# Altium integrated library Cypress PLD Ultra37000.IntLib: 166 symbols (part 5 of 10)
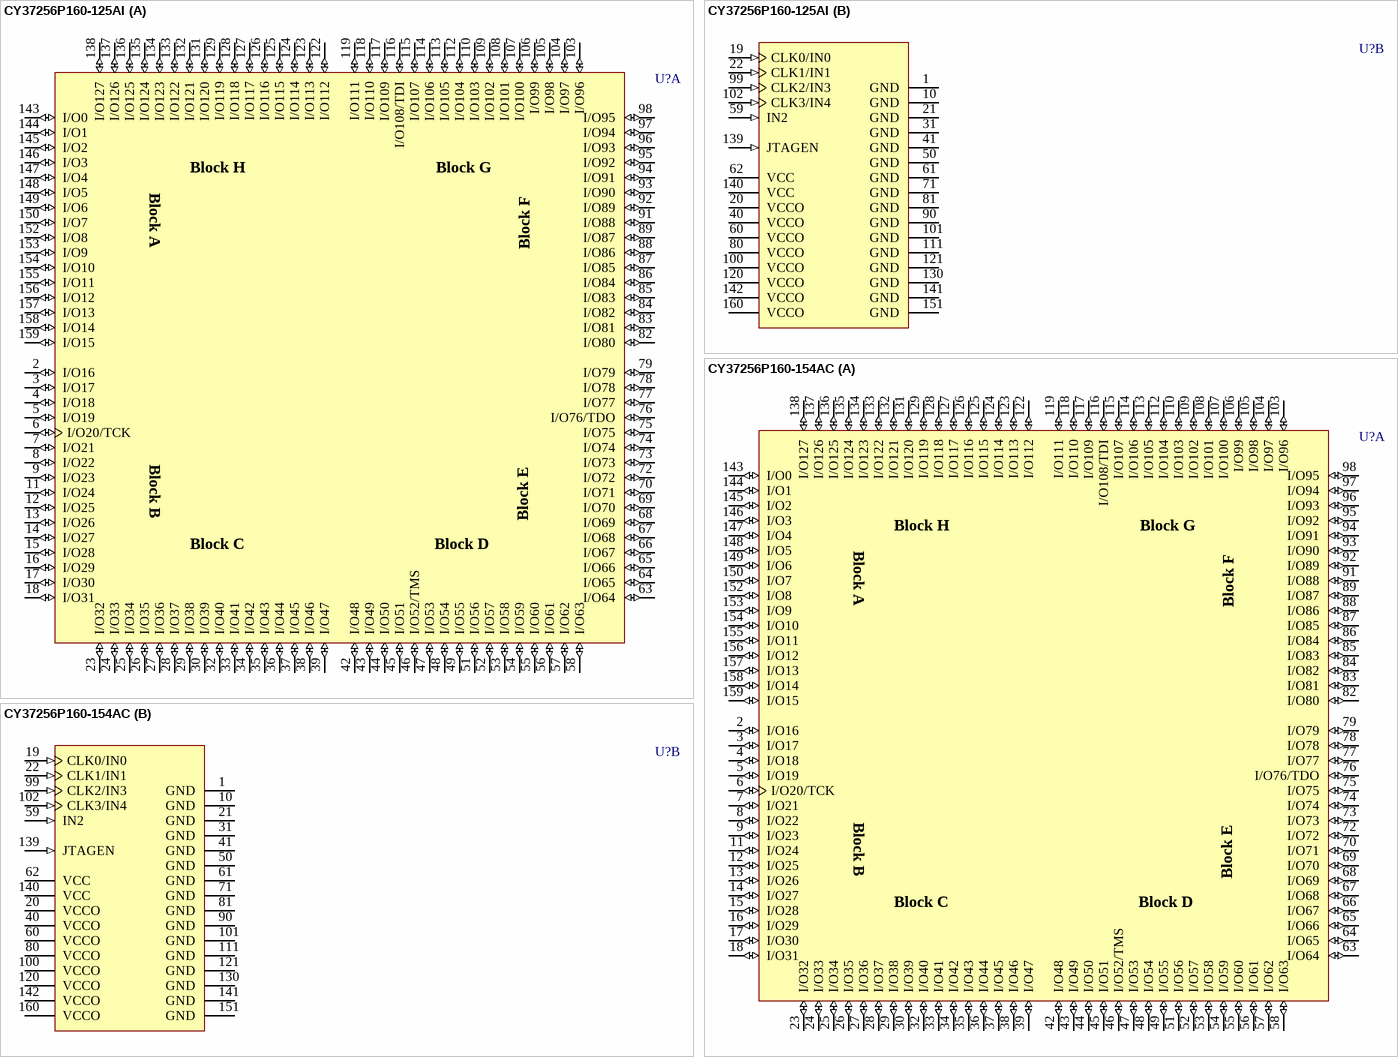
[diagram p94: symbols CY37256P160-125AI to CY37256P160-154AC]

## CY37256P160-154AC
designator U?
Ultra37000 5V, ISR High-Performance CPLD
footprint A160_N (Thin QFP, 160-Leads, Body 24x24mm, Pitch 0.5mm, IPC Medium Density)
footprint A160_L (Thin QFP, 160-Leads, Body 24x24mm, Pitch 0.5mm, IPC High Density)
footprint A160_M (Thin QFP, 160-Leads, Body 24x24mm, Pitch 0.5mm, IPC Low Density)
3D model CY37256P160-A160 (160-Pin Thin Quad Flat Pack 0.5 mm Pitch)
part A pins: 2 I/O16 (io), 3 I/O17 (io), 4 I/O18 (io), 5 I/O19 (io), 6 I/O20/TCK (io), 7 I/O21 (io), 8 I/O22 (io), 9 I/O23 (io), 11 I/O24 (io), 12 I/O25 (io), 13 I/O26 (io), 14 I/O27 (io), 15 I/O28 (io), 16 I/O29 (io), 17 I/O30 (io), 18 I/O31 (io), 23 I/O32 (io), 24 I/O33 (io), 25 I/O34 (io), 26 I/O35 (io), 27 I/O36 (io), 28 I/O37 (io), 29 I/O38 (io), 30 I/O39 (io), 32 I/O40 (io), 33 I/O41 (io), 34 I/O42 (io), 35 I/O43 (io), 36 I/O44 (io), 37 I/O45 (io), 38 I/O46 (io), 39 I/O47 (io), 42 I/O48 (io), 43 I/O49 (io), 44 I/O50 (io), 45 I/O51 (io), 46 I/O52/TMS (io), 47 I/O53 (io), 48 I/O54 (io), 49 I/O55 (io), 51 I/O56 (io), 52 I/O57 (io), 53 I/O58 (io), 54 I/O59 (io), 55 I/O60 (io), 56 I/O61 (io), 57 I/O62 (io), 58 I/O63 (io), 63 I/O64 (io), 64 I/O65 (io), 65 I/O66 (io), 66 I/O67 (io), 67 I/O68 (io), 68 I/O69 (io), 69 I/O70 (io), 70 I/O71 (io), 72 I/O72 (io), 73 I/O73 (io), 74 I/O74 (io), 75 I/O75 (io), 76 I/O76/TDO (io), 77 I/O77 (io), 78 I/O78 (io), 79 I/O79 (io), 82 I/O80 (io), 83 I/O81 (io), 84 I/O82 (io), 85 I/O83 (io), 86 I/O84 (io), 87 I/O85 (io), 88 I/O86 (io), 89 I/O87 (io), 91 I/O88 (io), 92 I/O89 (io), 93 I/O90 (io), 94 I/O91 (io), 95 I/O92 (io), 96 I/O93 (io), 97 I/O94 (io), 98 I/O95 (io), 103 I/O96 (io), 104 I/O97 (io), 105 I/O98 (io), 106 I/O99 (io), 107 I/O100 (io), 108 I/O101 (io), 109 I/O102 (io), 110 I/O103 (io), 112 I/O104 (io), 113 I/O105 (io), 114 I/O106 (io), 115 I/O107 (io), 116 I/O108/TDI (io), 117 I/O109 (io), 118 I/O110 (io), 119 I/O111 (io), 122 I/O112 (io), 123 I/O113 (io), 124 I/O114 (io), 125 I/O115 (io), 126 I/O116 (io), 127 I/O117 (io), 128 I/O118 (io), 129 I/O119 (io), 131 I/O120 (io), 132 I/O121 (io), 133 I/O122 (io), 134 I/O123 (io), 135 I/O124 (io), 136 I/O125 (io), 137 I/O126 (io), 138 I/O127 (io), 143 I/O0 (io), 144 I/O1 (io), 145 I/O2 (io), 146 I/O3 (io), 147 I/O4 (io), 148 I/O5 (io), 149 I/O6 (io), 150 I/O7 (io), 152 I/O8 (io), 153 I/O9 (io), 154 I/O10 (io), 155 I/O11 (io), 156 I/O12 (io), 157 I/O13 (io), 158 I/O14 (io), 159 I/O15 (io)
part B pins: 1 GND (power), 10 GND (power), 19 CLK0/IN0 (in), 20 VCCO (power), 21 GND (power), 22 CLK1/IN1 (in), 31 GND (power), 40 VCCO (power), 41 GND (power), 50 GND (power), 59 IN2 (in), 60 VCCO (power), 61 GND (power), 62 VCC (power), 71 GND (power), 80 VCCO (power), 81 GND (power), 90 GND (power), 99 CLK2/IN3 (in), 100 VCCO (power), 101 GND (power), 102 CLK3/IN4 (in), 111 GND (power), 120 VCCO (power), 121 GND (power), 130 GND (power), 139 JTAGEN (in), 140 VCC (power), 141 GND (power), 142 VCCO (power), 151 GND (power), 160 VCCO (power)

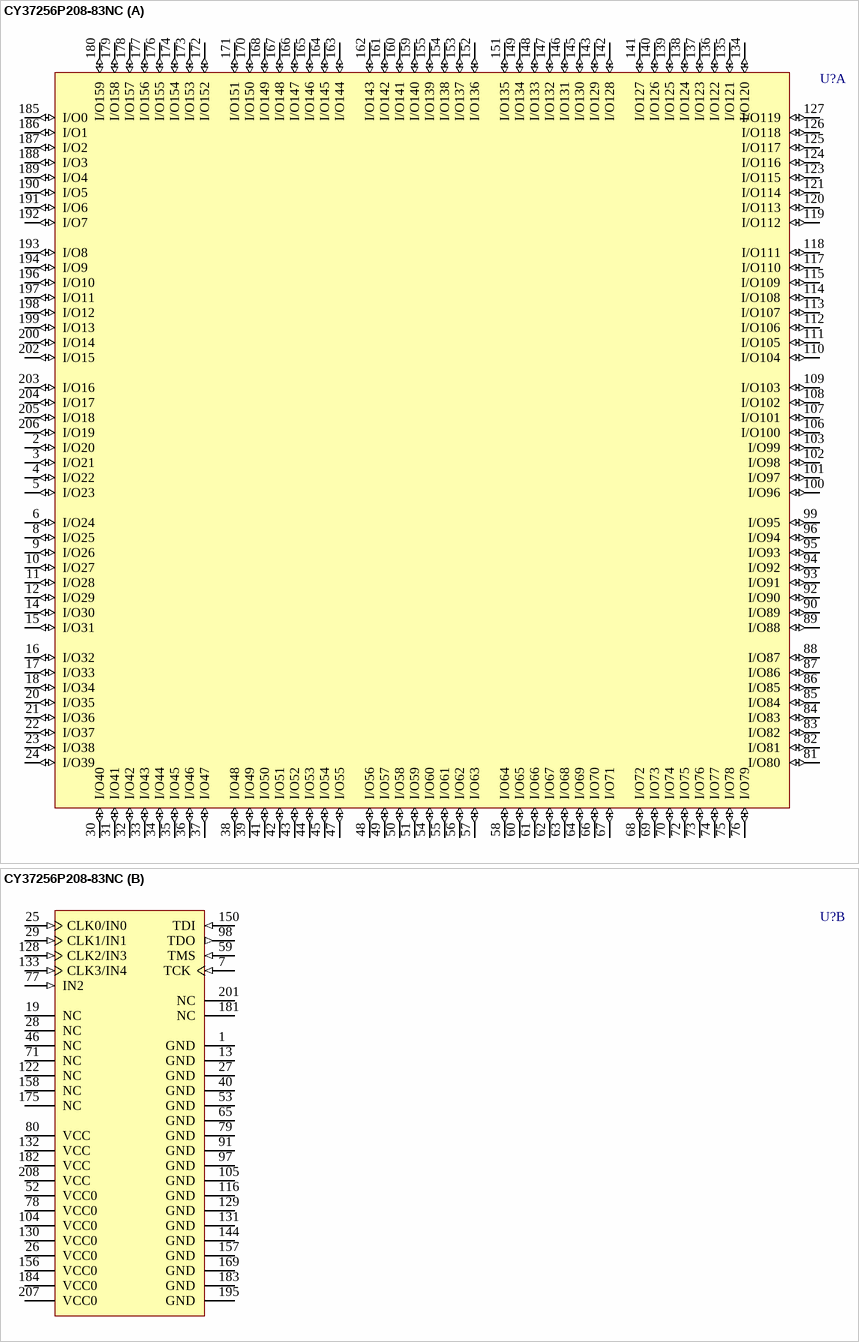
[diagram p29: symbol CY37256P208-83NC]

## CY37256P208-83NC
designator U?
Ultra37000 5V, ISR High-Performance CPLD
footprint N208_N (Shrink QFP, 208-Leads, Body 28x28mm, Pitch 0.5mm, IPC Medium Density)
footprint N208_L (Shrink QFP, 208-Leads, Body 28x28mm, Pitch 0.5mm, IPC High Density)
footprint N208_M (Shrink QFP, 208-Leads, Body 28x28mm, Pitch 0.5mm, IPC Low Density)
3D model CY37256P208-N208 (208-Pin Plastic Shrink Quad Flat Pack 0.5 mm Pitch)
part A pins: 2 I/O20 (io), 3 I/O21 (io), 4 I/O22 (io), 5 I/O23 (io), 6 I/O24 (io), 8 I/O25 (io), 9 I/O26 (io), 10 I/O27 (io), 11 I/O28 (io), 12 I/O29 (io), 14 I/O30 (io), 15 I/O31 (io), 16 I/O32 (io), 17 I/O33 (io), 18 I/O34 (io), 20 I/O35 (io), 21 I/O36 (io), 22 I/O37 (io), 23 I/O38 (io), 24 I/O39 (io), 30 I/O40 (io), 31 I/O41 (io), 32 I/O42 (io), 33 I/O43 (io), 34 I/O44 (io), 35 I/O45 (io), 36 I/O46 (io), 37 I/O47 (io), 38 I/O48 (io), 39 I/O49 (io), 41 I/O50 (io), 42 I/O51 (io), 43 I/O52 (io), 44 I/O53 (io), 45 I/O54 (io), 47 I/O55 (io), 48 I/O56 (io), 49 I/O57 (io), 50 I/O58 (io), 51 I/O59 (io), 54 I/O60 (io), 55 I/O61 (io), 56 I/O62 (io), 57 I/O63 (io), 58 I/O64 (io), 60 I/O65 (io), 61 I/O66 (io), 62 I/O67 (io), 63 I/O68 (io), 64 I/O69 (io), 66 I/O70 (io), 67 I/O71 (io), 68 I/O72 (io), 69 I/O73 (io), 70 I/O74 (io), 72 I/O75 (io), 73 I/O76 (io), 74 I/O77 (io), 75 I/O78 (io), 76 I/O79 (io), 81 I/O80 (io), 82 I/O81 (io), 83 I/O82 (io), 84 I/O83 (io), 85 I/O84 (io), 86 I/O85 (io), 87 I/O86 (io), 88 I/O87 (io), 89 I/O88 (io), 90 I/O89 (io), 92 I/O90 (io), 93 I/O91 (io), 94 I/O92 (io), 95 I/O93 (io), 96 I/O94 (io), 99 I/O95 (io), 100 I/O96 (io), 101 I/O97 (io), 102 I/O98 (io), 103 I/O99 (io), 106 I/O100 (io), 107 I/O101 (io), 108 I/O102 (io), 109 I/O103 (io), 110 I/O104 (io), 111 I/O105 (io), 112 I/O106 (io), 113 I/O107 (io), 114 I/O108 (io), 115 I/O109 (io), 117 I/O110 (io), 118 I/O111 (io), 119 I/O112 (io), 120 I/O113 (io), 121 I/O114 (io), 123 I/O115 (io), 124 I/O116 (io), 125 I/O117 (io), 126 I/O118 (io), 127 I/O119 (io), 134 I/O120 (io), 135 I/O121 (io), 136 I/O122 (io), 137 I/O123 (io), 138 I/O124 (io), 139 I/O125 (io), 140 I/O126 (io), 141 I/O127 (io), 142 I/O128 (io), 143 I/O129 (io), 145 I/O130 (io), 146 I/O131 (io), 147 I/O132 (io), 148 I/O133 (io), 149 I/O134 (io), 151 I/O135 (io), 152 I/O136 (io), 153 I/O137 (io), 154 I/O138 (io), 155 I/O139 (io), 159 I/O140 (io), 160 I/O141 (io), 161 I/O142 (io), 162 I/O143 (io), 163 I/O144 (io), 164 I/O145 (io), 165 I/O146 (io), 166 I/O147 (io), 167 I/O148 (io), 168 I/O149 (io), 170 I/O150 (io), 171 I/O151 (io), 172 I/O152 (io), 173 I/O153 (io), 174 I/O154 (io), 176 I/O155 (io), 177 I/O156 (io), 178 I/O157 (io), 179 I/O158 (io), 180 I/O159 (io), 185 I/O0 (io), 186 I/O1 (io), 187 I/O2 (io), 188 I/O3 (io), 189 I/O4 (io), 190 I/O5 (io), 191 I/O6 (io), 192 I/O7 (io), 193 I/O8 (io), 194 I/O9 (io), 196 I/O10 (io), 197 I/O11 (io), 198 I/O12 (io), 199 I/O13 (io), 200 I/O14 (io), 202 I/O15 (io), 203 I/O16 (io), 204 I/O17 (io), 205 I/O18 (io), 206 I/O19 (io)
part B pins: 1 GND (power), 7 TCK (in), 13 GND (power), 19 NC, 25 CLK0/IN0 (in), 26 VCC0 (power), 27 GND (power), 28 NC, 29 CLK1/IN1 (in), 40 GND (power), 46 NC, 52 VCC0 (power), 53 GND (power), 59 TMS (in), 65 GND (power), 71 NC, 77 IN2 (in), 78 VCC0 (power), 79 GND (power), 80 VCC (power), 91 GND (power), 97 GND (power), 98 TDO (out), 104 VCC0 (power), 105 GND (power), 116 GND (power), 122 NC, 128 CLK2/IN3 (in), 129 GND (power), 130 VCC0 (power), 131 GND (power), 132 VCC (power), 133 CLK3/IN4 (in), 144 GND (power), 150 TDI (in), 156 VCC0 (power), 157 GND (power), 158 NC, 169 GND (power), 175 NC, 181 NC, 182 VCC (power), 183 GND (power), 184 VCC0 (power), 195 GND (power), 201 NC, 207 VCC0 (power), 208 VCC (power)

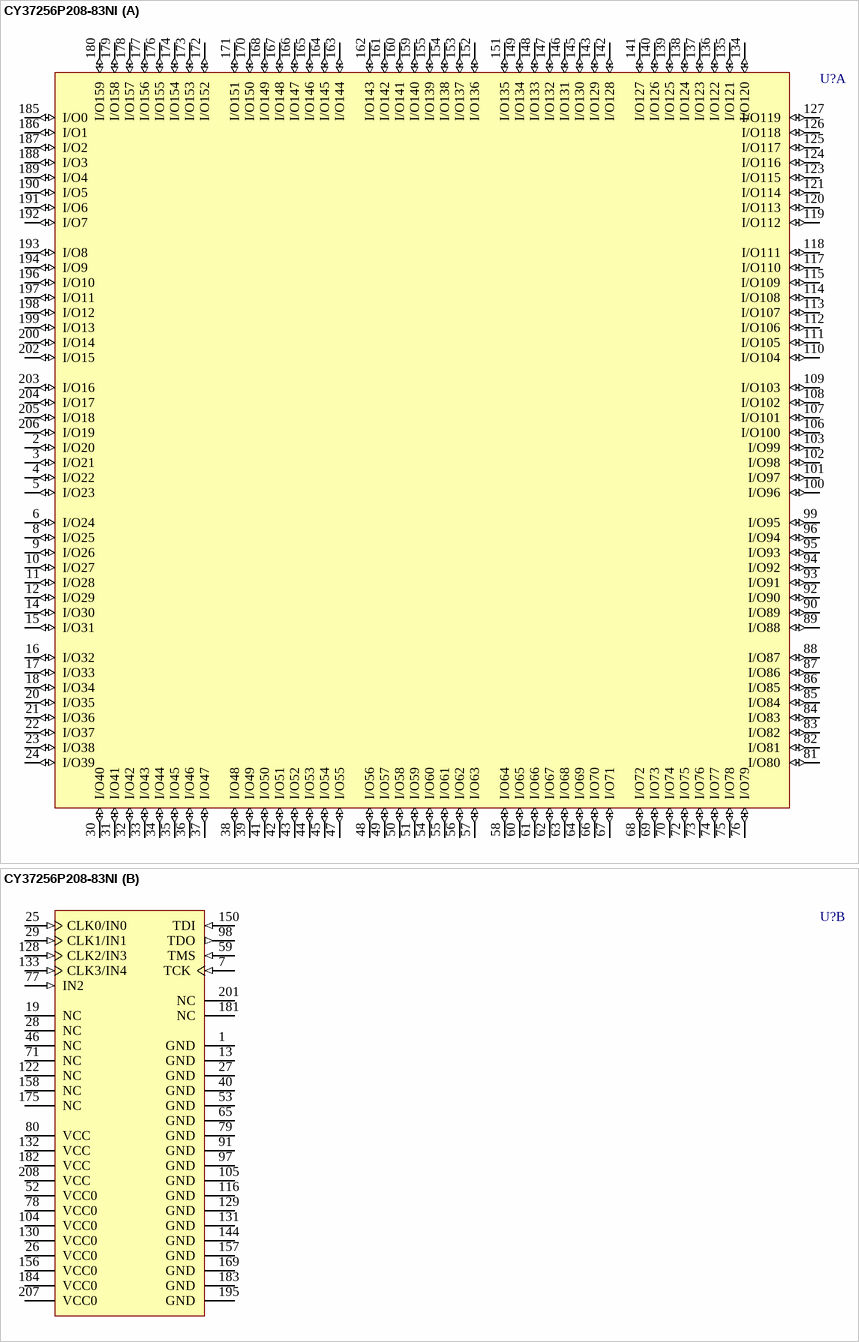
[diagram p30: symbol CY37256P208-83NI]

## CY37256P208-83NI
designator U?
Ultra37000 5V, ISR High-Performance CPLD
footprint N208_N (Shrink QFP, 208-Leads, Body 28x28mm, Pitch 0.5mm, IPC Medium Density)
footprint N208_L (Shrink QFP, 208-Leads, Body 28x28mm, Pitch 0.5mm, IPC High Density)
footprint N208_M (Shrink QFP, 208-Leads, Body 28x28mm, Pitch 0.5mm, IPC Low Density)
3D model CY37256P208-N208 (208-Pin Plastic Shrink Quad Flat Pack 0.5 mm Pitch)
part A pins: 2 I/O20 (io), 3 I/O21 (io), 4 I/O22 (io), 5 I/O23 (io), 6 I/O24 (io), 8 I/O25 (io), 9 I/O26 (io), 10 I/O27 (io), 11 I/O28 (io), 12 I/O29 (io), 14 I/O30 (io), 15 I/O31 (io), 16 I/O32 (io), 17 I/O33 (io), 18 I/O34 (io), 20 I/O35 (io), 21 I/O36 (io), 22 I/O37 (io), 23 I/O38 (io), 24 I/O39 (io), 30 I/O40 (io), 31 I/O41 (io), 32 I/O42 (io), 33 I/O43 (io), 34 I/O44 (io), 35 I/O45 (io), 36 I/O46 (io), 37 I/O47 (io), 38 I/O48 (io), 39 I/O49 (io), 41 I/O50 (io), 42 I/O51 (io), 43 I/O52 (io), 44 I/O53 (io), 45 I/O54 (io), 47 I/O55 (io), 48 I/O56 (io), 49 I/O57 (io), 50 I/O58 (io), 51 I/O59 (io), 54 I/O60 (io), 55 I/O61 (io), 56 I/O62 (io), 57 I/O63 (io), 58 I/O64 (io), 60 I/O65 (io), 61 I/O66 (io), 62 I/O67 (io), 63 I/O68 (io), 64 I/O69 (io), 66 I/O70 (io), 67 I/O71 (io), 68 I/O72 (io), 69 I/O73 (io), 70 I/O74 (io), 72 I/O75 (io), 73 I/O76 (io), 74 I/O77 (io), 75 I/O78 (io), 76 I/O79 (io), 81 I/O80 (io), 82 I/O81 (io), 83 I/O82 (io), 84 I/O83 (io), 85 I/O84 (io), 86 I/O85 (io), 87 I/O86 (io), 88 I/O87 (io), 89 I/O88 (io), 90 I/O89 (io), 92 I/O90 (io), 93 I/O91 (io), 94 I/O92 (io), 95 I/O93 (io), 96 I/O94 (io), 99 I/O95 (io), 100 I/O96 (io), 101 I/O97 (io), 102 I/O98 (io), 103 I/O99 (io), 106 I/O100 (io), 107 I/O101 (io), 108 I/O102 (io), 109 I/O103 (io), 110 I/O104 (io), 111 I/O105 (io), 112 I/O106 (io), 113 I/O107 (io), 114 I/O108 (io), 115 I/O109 (io), 117 I/O110 (io), 118 I/O111 (io), 119 I/O112 (io), 120 I/O113 (io), 121 I/O114 (io), 123 I/O115 (io), 124 I/O116 (io), 125 I/O117 (io), 126 I/O118 (io), 127 I/O119 (io), 134 I/O120 (io), 135 I/O121 (io), 136 I/O122 (io), 137 I/O123 (io), 138 I/O124 (io), 139 I/O125 (io), 140 I/O126 (io), 141 I/O127 (io), 142 I/O128 (io), 143 I/O129 (io), 145 I/O130 (io), 146 I/O131 (io), 147 I/O132 (io), 148 I/O133 (io), 149 I/O134 (io), 151 I/O135 (io), 152 I/O136 (io), 153 I/O137 (io), 154 I/O138 (io), 155 I/O139 (io), 159 I/O140 (io), 160 I/O141 (io), 161 I/O142 (io), 162 I/O143 (io), 163 I/O144 (io), 164 I/O145 (io), 165 I/O146 (io), 166 I/O147 (io), 167 I/O148 (io), 168 I/O149 (io), 170 I/O150 (io), 171 I/O151 (io), 172 I/O152 (io), 173 I/O153 (io), 174 I/O154 (io), 176 I/O155 (io), 177 I/O156 (io), 178 I/O157 (io), 179 I/O158 (io), 180 I/O159 (io), 185 I/O0 (io), 186 I/O1 (io), 187 I/O2 (io), 188 I/O3 (io), 189 I/O4 (io), 190 I/O5 (io), 191 I/O6 (io), 192 I/O7 (io), 193 I/O8 (io), 194 I/O9 (io), 196 I/O10 (io), 197 I/O11 (io), 198 I/O12 (io), 199 I/O13 (io), 200 I/O14 (io), 202 I/O15 (io), 203 I/O16 (io), 204 I/O17 (io), 205 I/O18 (io), 206 I/O19 (io)
part B pins: 1 GND (power), 7 TCK (in), 13 GND (power), 19 NC, 25 CLK0/IN0 (in), 26 VCC0 (power), 27 GND (power), 28 NC, 29 CLK1/IN1 (in), 40 GND (power), 46 NC, 52 VCC0 (power), 53 GND (power), 59 TMS (in), 65 GND (power), 71 NC, 77 IN2 (in), 78 VCC0 (power), 79 GND (power), 80 VCC (power), 91 GND (power), 97 GND (power), 98 TDO (out), 104 VCC0 (power), 105 GND (power), 116 GND (power), 122 NC, 128 CLK2/IN3 (in), 129 GND (power), 130 VCC0 (power), 131 GND (power), 132 VCC (power), 133 CLK3/IN4 (in), 144 GND (power), 150 TDI (in), 156 VCC0 (power), 157 GND (power), 158 NC, 169 GND (power), 175 NC, 181 NC, 182 VCC (power), 183 GND (power), 184 VCC0 (power), 195 GND (power), 201 NC, 207 VCC0 (power), 208 VCC (power)

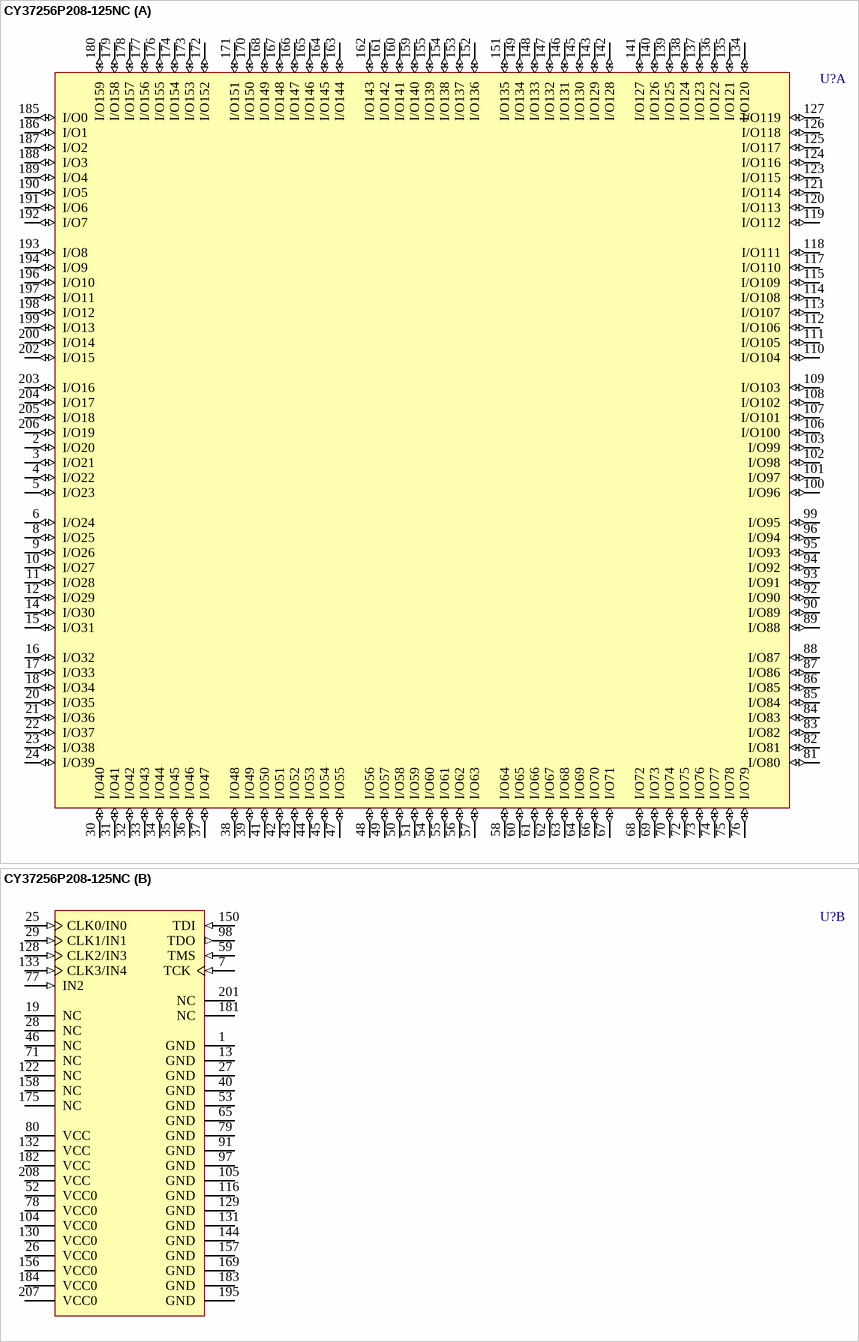
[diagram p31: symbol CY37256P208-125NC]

## CY37256P208-125NC
designator U?
Ultra37000 5V, ISR High-Performance CPLD
footprint N208_N (Shrink QFP, 208-Leads, Body 28x28mm, Pitch 0.5mm, IPC Medium Density)
footprint N208_L (Shrink QFP, 208-Leads, Body 28x28mm, Pitch 0.5mm, IPC High Density)
footprint N208_M (Shrink QFP, 208-Leads, Body 28x28mm, Pitch 0.5mm, IPC Low Density)
3D model CY37256P208-N208 (208-Pin Plastic Shrink Quad Flat Pack 0.5 mm Pitch)
part A pins: 2 I/O20 (io), 3 I/O21 (io), 4 I/O22 (io), 5 I/O23 (io), 6 I/O24 (io), 8 I/O25 (io), 9 I/O26 (io), 10 I/O27 (io), 11 I/O28 (io), 12 I/O29 (io), 14 I/O30 (io), 15 I/O31 (io), 16 I/O32 (io), 17 I/O33 (io), 18 I/O34 (io), 20 I/O35 (io), 21 I/O36 (io), 22 I/O37 (io), 23 I/O38 (io), 24 I/O39 (io), 30 I/O40 (io), 31 I/O41 (io), 32 I/O42 (io), 33 I/O43 (io), 34 I/O44 (io), 35 I/O45 (io), 36 I/O46 (io), 37 I/O47 (io), 38 I/O48 (io), 39 I/O49 (io), 41 I/O50 (io), 42 I/O51 (io), 43 I/O52 (io), 44 I/O53 (io), 45 I/O54 (io), 47 I/O55 (io), 48 I/O56 (io), 49 I/O57 (io), 50 I/O58 (io), 51 I/O59 (io), 54 I/O60 (io), 55 I/O61 (io), 56 I/O62 (io), 57 I/O63 (io), 58 I/O64 (io), 60 I/O65 (io), 61 I/O66 (io), 62 I/O67 (io), 63 I/O68 (io), 64 I/O69 (io), 66 I/O70 (io), 67 I/O71 (io), 68 I/O72 (io), 69 I/O73 (io), 70 I/O74 (io), 72 I/O75 (io), 73 I/O76 (io), 74 I/O77 (io), 75 I/O78 (io), 76 I/O79 (io), 81 I/O80 (io), 82 I/O81 (io), 83 I/O82 (io), 84 I/O83 (io), 85 I/O84 (io), 86 I/O85 (io), 87 I/O86 (io), 88 I/O87 (io), 89 I/O88 (io), 90 I/O89 (io), 92 I/O90 (io), 93 I/O91 (io), 94 I/O92 (io), 95 I/O93 (io), 96 I/O94 (io), 99 I/O95 (io), 100 I/O96 (io), 101 I/O97 (io), 102 I/O98 (io), 103 I/O99 (io), 106 I/O100 (io), 107 I/O101 (io), 108 I/O102 (io), 109 I/O103 (io), 110 I/O104 (io), 111 I/O105 (io), 112 I/O106 (io), 113 I/O107 (io), 114 I/O108 (io), 115 I/O109 (io), 117 I/O110 (io), 118 I/O111 (io), 119 I/O112 (io), 120 I/O113 (io), 121 I/O114 (io), 123 I/O115 (io), 124 I/O116 (io), 125 I/O117 (io), 126 I/O118 (io), 127 I/O119 (io), 134 I/O120 (io), 135 I/O121 (io), 136 I/O122 (io), 137 I/O123 (io), 138 I/O124 (io), 139 I/O125 (io), 140 I/O126 (io), 141 I/O127 (io), 142 I/O128 (io), 143 I/O129 (io), 145 I/O130 (io), 146 I/O131 (io), 147 I/O132 (io), 148 I/O133 (io), 149 I/O134 (io), 151 I/O135 (io), 152 I/O136 (io), 153 I/O137 (io), 154 I/O138 (io), 155 I/O139 (io), 159 I/O140 (io), 160 I/O141 (io), 161 I/O142 (io), 162 I/O143 (io), 163 I/O144 (io), 164 I/O145 (io), 165 I/O146 (io), 166 I/O147 (io), 167 I/O148 (io), 168 I/O149 (io), 170 I/O150 (io), 171 I/O151 (io), 172 I/O152 (io), 173 I/O153 (io), 174 I/O154 (io), 176 I/O155 (io), 177 I/O156 (io), 178 I/O157 (io), 179 I/O158 (io), 180 I/O159 (io), 185 I/O0 (io), 186 I/O1 (io), 187 I/O2 (io), 188 I/O3 (io), 189 I/O4 (io), 190 I/O5 (io), 191 I/O6 (io), 192 I/O7 (io), 193 I/O8 (io), 194 I/O9 (io), 196 I/O10 (io), 197 I/O11 (io), 198 I/O12 (io), 199 I/O13 (io), 200 I/O14 (io), 202 I/O15 (io), 203 I/O16 (io), 204 I/O17 (io), 205 I/O18 (io), 206 I/O19 (io)
part B pins: 1 GND (power), 7 TCK (in), 13 GND (power), 19 NC, 25 CLK0/IN0 (in), 26 VCC0 (power), 27 GND (power), 28 NC, 29 CLK1/IN1 (in), 40 GND (power), 46 NC, 52 VCC0 (power), 53 GND (power), 59 TMS (in), 65 GND (power), 71 NC, 77 IN2 (in), 78 VCC0 (power), 79 GND (power), 80 VCC (power), 91 GND (power), 97 GND (power), 98 TDO (out), 104 VCC0 (power), 105 GND (power), 116 GND (power), 122 NC, 128 CLK2/IN3 (in), 129 GND (power), 130 VCC0 (power), 131 GND (power), 132 VCC (power), 133 CLK3/IN4 (in), 144 GND (power), 150 TDI (in), 156 VCC0 (power), 157 GND (power), 158 NC, 169 GND (power), 175 NC, 181 NC, 182 VCC (power), 183 GND (power), 184 VCC0 (power), 195 GND (power), 201 NC, 207 VCC0 (power), 208 VCC (power)

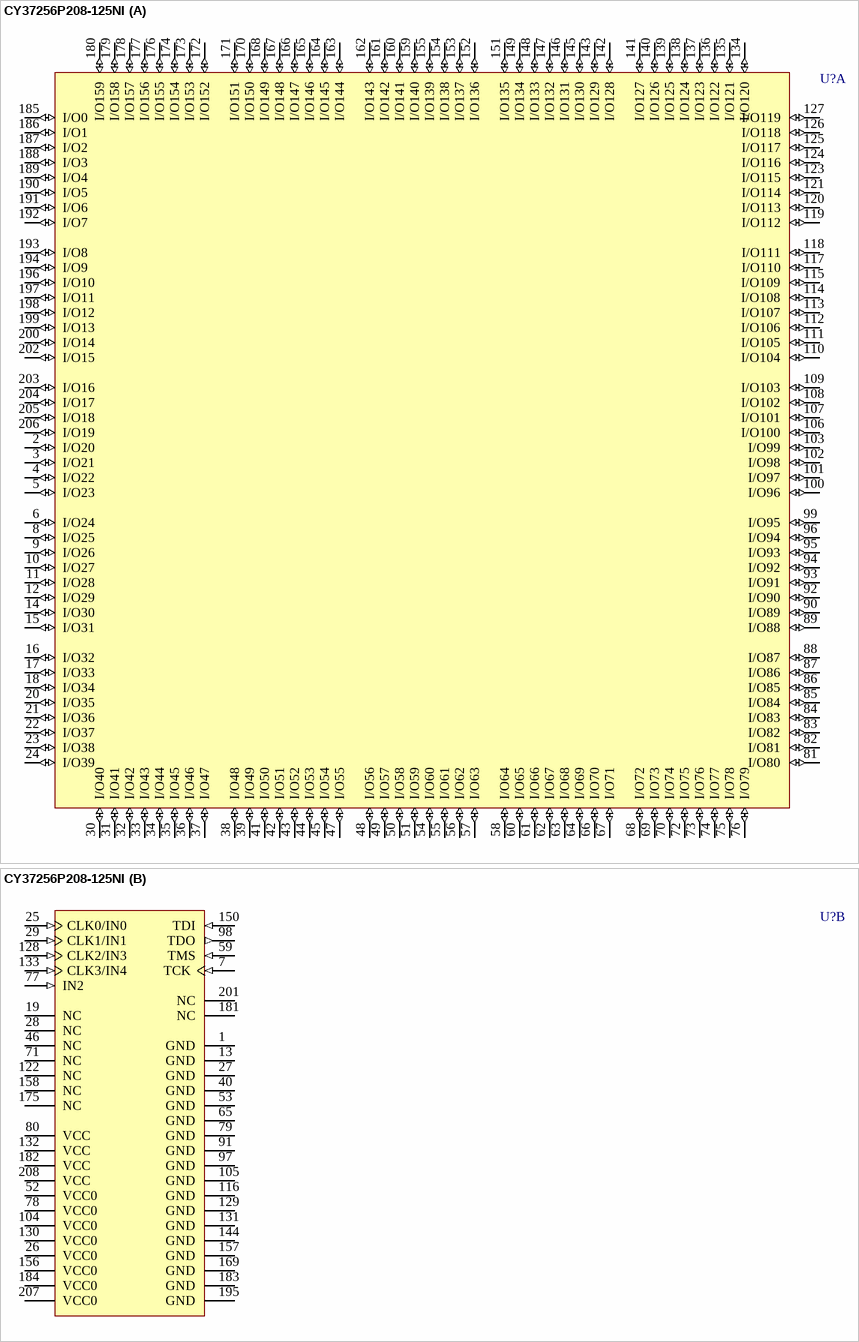
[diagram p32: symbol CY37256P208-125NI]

## CY37256P208-125NI
designator U?
Ultra37000 5V, ISR High-Performance CPLD
footprint N208_N (Shrink QFP, 208-Leads, Body 28x28mm, Pitch 0.5mm, IPC Medium Density)
footprint N208_L (Shrink QFP, 208-Leads, Body 28x28mm, Pitch 0.5mm, IPC High Density)
footprint N208_M (Shrink QFP, 208-Leads, Body 28x28mm, Pitch 0.5mm, IPC Low Density)
3D model CY37256P208-N208 (208-Pin Plastic Shrink Quad Flat Pack 0.5 mm Pitch)
part A pins: 2 I/O20 (io), 3 I/O21 (io), 4 I/O22 (io), 5 I/O23 (io), 6 I/O24 (io), 8 I/O25 (io), 9 I/O26 (io), 10 I/O27 (io), 11 I/O28 (io), 12 I/O29 (io), 14 I/O30 (io), 15 I/O31 (io), 16 I/O32 (io), 17 I/O33 (io), 18 I/O34 (io), 20 I/O35 (io), 21 I/O36 (io), 22 I/O37 (io), 23 I/O38 (io), 24 I/O39 (io), 30 I/O40 (io), 31 I/O41 (io), 32 I/O42 (io), 33 I/O43 (io), 34 I/O44 (io), 35 I/O45 (io), 36 I/O46 (io), 37 I/O47 (io), 38 I/O48 (io), 39 I/O49 (io), 41 I/O50 (io), 42 I/O51 (io), 43 I/O52 (io), 44 I/O53 (io), 45 I/O54 (io), 47 I/O55 (io), 48 I/O56 (io), 49 I/O57 (io), 50 I/O58 (io), 51 I/O59 (io), 54 I/O60 (io), 55 I/O61 (io), 56 I/O62 (io), 57 I/O63 (io), 58 I/O64 (io), 60 I/O65 (io), 61 I/O66 (io), 62 I/O67 (io), 63 I/O68 (io), 64 I/O69 (io), 66 I/O70 (io), 67 I/O71 (io), 68 I/O72 (io), 69 I/O73 (io), 70 I/O74 (io), 72 I/O75 (io), 73 I/O76 (io), 74 I/O77 (io), 75 I/O78 (io), 76 I/O79 (io), 81 I/O80 (io), 82 I/O81 (io), 83 I/O82 (io), 84 I/O83 (io), 85 I/O84 (io), 86 I/O85 (io), 87 I/O86 (io), 88 I/O87 (io), 89 I/O88 (io), 90 I/O89 (io), 92 I/O90 (io), 93 I/O91 (io), 94 I/O92 (io), 95 I/O93 (io), 96 I/O94 (io), 99 I/O95 (io), 100 I/O96 (io), 101 I/O97 (io), 102 I/O98 (io), 103 I/O99 (io), 106 I/O100 (io), 107 I/O101 (io), 108 I/O102 (io), 109 I/O103 (io), 110 I/O104 (io), 111 I/O105 (io), 112 I/O106 (io), 113 I/O107 (io), 114 I/O108 (io), 115 I/O109 (io), 117 I/O110 (io), 118 I/O111 (io), 119 I/O112 (io), 120 I/O113 (io), 121 I/O114 (io), 123 I/O115 (io), 124 I/O116 (io), 125 I/O117 (io), 126 I/O118 (io), 127 I/O119 (io), 134 I/O120 (io), 135 I/O121 (io), 136 I/O122 (io), 137 I/O123 (io), 138 I/O124 (io), 139 I/O125 (io), 140 I/O126 (io), 141 I/O127 (io), 142 I/O128 (io), 143 I/O129 (io), 145 I/O130 (io), 146 I/O131 (io), 147 I/O132 (io), 148 I/O133 (io), 149 I/O134 (io), 151 I/O135 (io), 152 I/O136 (io), 153 I/O137 (io), 154 I/O138 (io), 155 I/O139 (io), 159 I/O140 (io), 160 I/O141 (io), 161 I/O142 (io), 162 I/O143 (io), 163 I/O144 (io), 164 I/O145 (io), 165 I/O146 (io), 166 I/O147 (io), 167 I/O148 (io), 168 I/O149 (io), 170 I/O150 (io), 171 I/O151 (io), 172 I/O152 (io), 173 I/O153 (io), 174 I/O154 (io), 176 I/O155 (io), 177 I/O156 (io), 178 I/O157 (io), 179 I/O158 (io), 180 I/O159 (io), 185 I/O0 (io), 186 I/O1 (io), 187 I/O2 (io), 188 I/O3 (io), 189 I/O4 (io), 190 I/O5 (io), 191 I/O6 (io), 192 I/O7 (io), 193 I/O8 (io), 194 I/O9 (io), 196 I/O10 (io), 197 I/O11 (io), 198 I/O12 (io), 199 I/O13 (io), 200 I/O14 (io), 202 I/O15 (io), 203 I/O16 (io), 204 I/O17 (io), 205 I/O18 (io), 206 I/O19 (io)
part B pins: 1 GND (power), 7 TCK (in), 13 GND (power), 19 NC, 25 CLK0/IN0 (in), 26 VCC0 (power), 27 GND (power), 28 NC, 29 CLK1/IN1 (in), 40 GND (power), 46 NC, 52 VCC0 (power), 53 GND (power), 59 TMS (in), 65 GND (power), 71 NC, 77 IN2 (in), 78 VCC0 (power), 79 GND (power), 80 VCC (power), 91 GND (power), 97 GND (power), 98 TDO (out), 104 VCC0 (power), 105 GND (power), 116 GND (power), 122 NC, 128 CLK2/IN3 (in), 129 GND (power), 130 VCC0 (power), 131 GND (power), 132 VCC (power), 133 CLK3/IN4 (in), 144 GND (power), 150 TDI (in), 156 VCC0 (power), 157 GND (power), 158 NC, 169 GND (power), 175 NC, 181 NC, 182 VCC (power), 183 GND (power), 184 VCC0 (power), 195 GND (power), 201 NC, 207 VCC0 (power), 208 VCC (power)

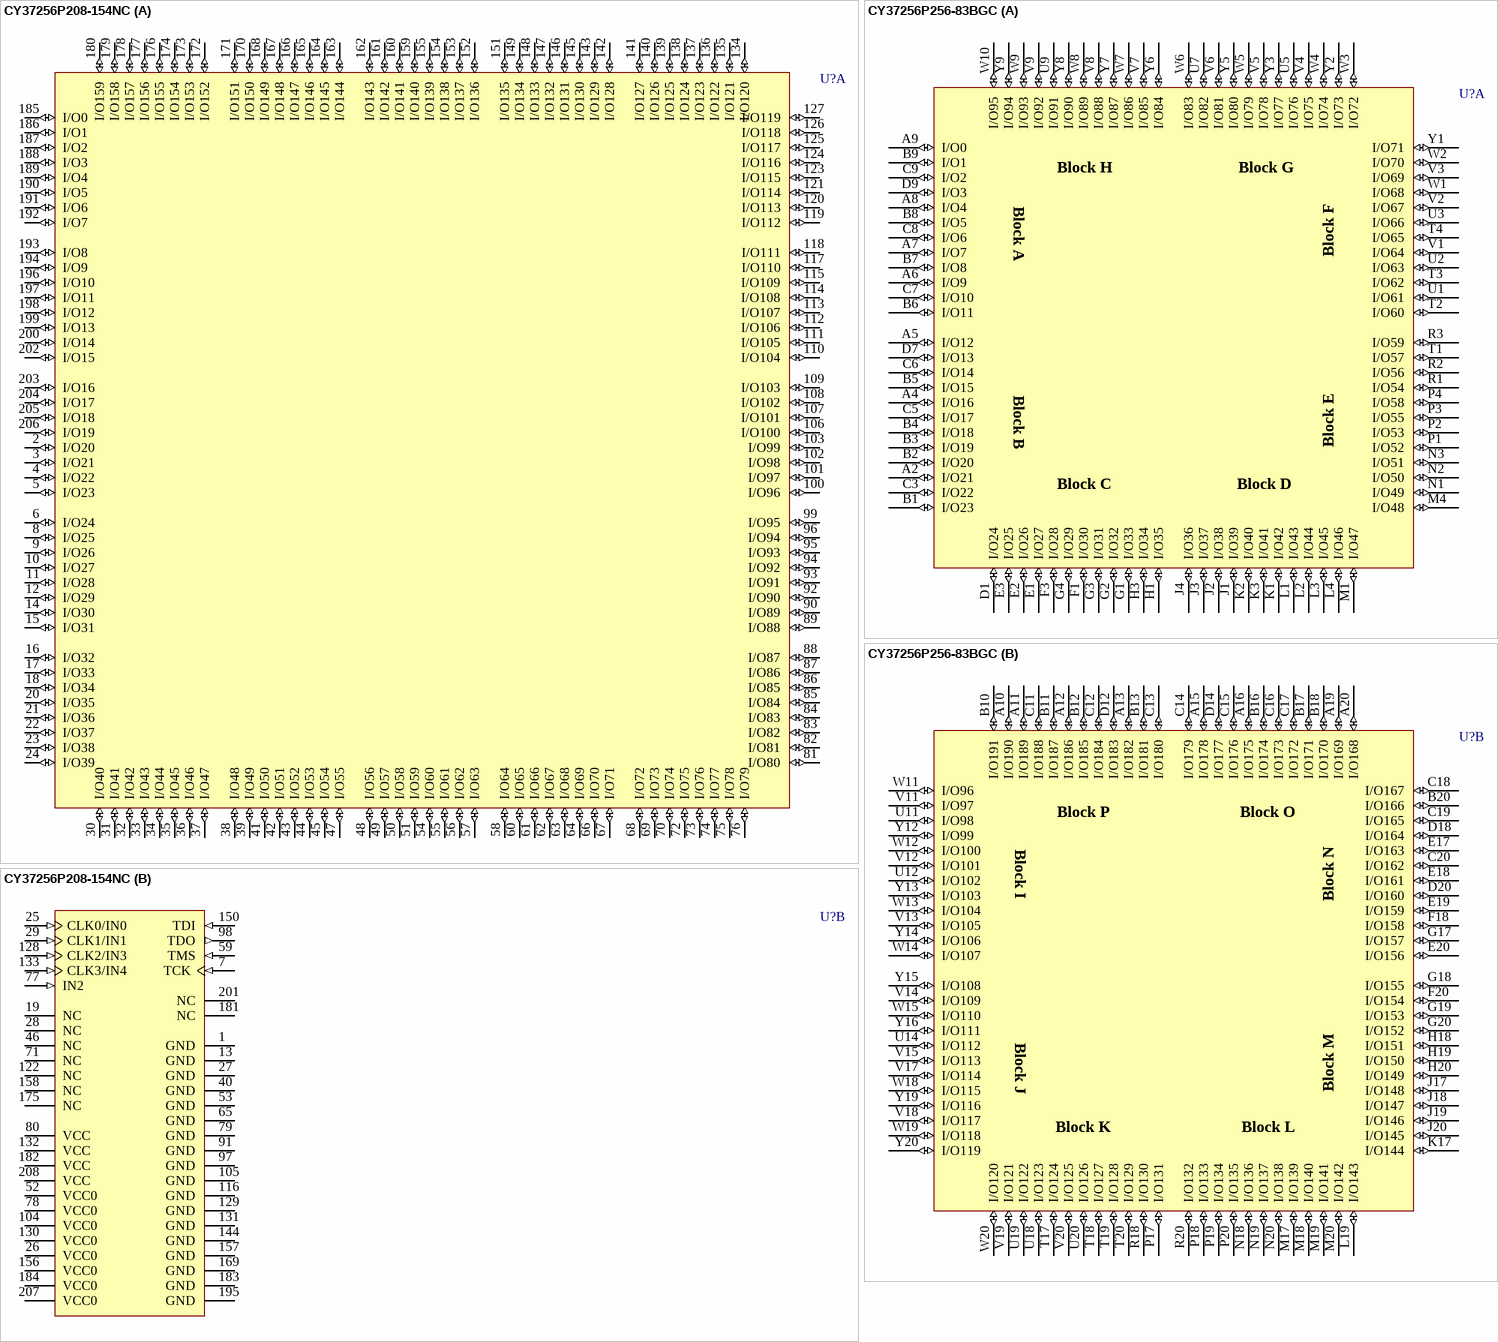
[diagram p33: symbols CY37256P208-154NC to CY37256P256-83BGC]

## CY37256P208-154NC
designator U?
Ultra37000 5V, ISR High-Performance CPLD
footprint N208_N (Shrink QFP, 208-Leads, Body 28x28mm, Pitch 0.5mm, IPC Medium Density)
footprint N208_L (Shrink QFP, 208-Leads, Body 28x28mm, Pitch 0.5mm, IPC High Density)
footprint N208_M (Shrink QFP, 208-Leads, Body 28x28mm, Pitch 0.5mm, IPC Low Density)
3D model CY37256P208-N208 (208-Pin Plastic Shrink Quad Flat Pack 0.5 mm Pitch)
part A pins: 2 I/O20 (io), 3 I/O21 (io), 4 I/O22 (io), 5 I/O23 (io), 6 I/O24 (io), 8 I/O25 (io), 9 I/O26 (io), 10 I/O27 (io), 11 I/O28 (io), 12 I/O29 (io), 14 I/O30 (io), 15 I/O31 (io), 16 I/O32 (io), 17 I/O33 (io), 18 I/O34 (io), 20 I/O35 (io), 21 I/O36 (io), 22 I/O37 (io), 23 I/O38 (io), 24 I/O39 (io), 30 I/O40 (io), 31 I/O41 (io), 32 I/O42 (io), 33 I/O43 (io), 34 I/O44 (io), 35 I/O45 (io), 36 I/O46 (io), 37 I/O47 (io), 38 I/O48 (io), 39 I/O49 (io), 41 I/O50 (io), 42 I/O51 (io), 43 I/O52 (io), 44 I/O53 (io), 45 I/O54 (io), 47 I/O55 (io), 48 I/O56 (io), 49 I/O57 (io), 50 I/O58 (io), 51 I/O59 (io), 54 I/O60 (io), 55 I/O61 (io), 56 I/O62 (io), 57 I/O63 (io), 58 I/O64 (io), 60 I/O65 (io), 61 I/O66 (io), 62 I/O67 (io), 63 I/O68 (io), 64 I/O69 (io), 66 I/O70 (io), 67 I/O71 (io), 68 I/O72 (io), 69 I/O73 (io), 70 I/O74 (io), 72 I/O75 (io), 73 I/O76 (io), 74 I/O77 (io), 75 I/O78 (io), 76 I/O79 (io), 81 I/O80 (io), 82 I/O81 (io), 83 I/O82 (io), 84 I/O83 (io), 85 I/O84 (io), 86 I/O85 (io), 87 I/O86 (io), 88 I/O87 (io), 89 I/O88 (io), 90 I/O89 (io), 92 I/O90 (io), 93 I/O91 (io), 94 I/O92 (io), 95 I/O93 (io), 96 I/O94 (io), 99 I/O95 (io), 100 I/O96 (io), 101 I/O97 (io), 102 I/O98 (io), 103 I/O99 (io), 106 I/O100 (io), 107 I/O101 (io), 108 I/O102 (io), 109 I/O103 (io), 110 I/O104 (io), 111 I/O105 (io), 112 I/O106 (io), 113 I/O107 (io), 114 I/O108 (io), 115 I/O109 (io), 117 I/O110 (io), 118 I/O111 (io), 119 I/O112 (io), 120 I/O113 (io), 121 I/O114 (io), 123 I/O115 (io), 124 I/O116 (io), 125 I/O117 (io), 126 I/O118 (io), 127 I/O119 (io), 134 I/O120 (io), 135 I/O121 (io), 136 I/O122 (io), 137 I/O123 (io), 138 I/O124 (io), 139 I/O125 (io), 140 I/O126 (io), 141 I/O127 (io), 142 I/O128 (io), 143 I/O129 (io), 145 I/O130 (io), 146 I/O131 (io), 147 I/O132 (io), 148 I/O133 (io), 149 I/O134 (io), 151 I/O135 (io), 152 I/O136 (io), 153 I/O137 (io), 154 I/O138 (io), 155 I/O139 (io), 159 I/O140 (io), 160 I/O141 (io), 161 I/O142 (io), 162 I/O143 (io), 163 I/O144 (io), 164 I/O145 (io), 165 I/O146 (io), 166 I/O147 (io), 167 I/O148 (io), 168 I/O149 (io), 170 I/O150 (io), 171 I/O151 (io), 172 I/O152 (io), 173 I/O153 (io), 174 I/O154 (io), 176 I/O155 (io), 177 I/O156 (io), 178 I/O157 (io), 179 I/O158 (io), 180 I/O159 (io), 185 I/O0 (io), 186 I/O1 (io), 187 I/O2 (io), 188 I/O3 (io), 189 I/O4 (io), 190 I/O5 (io), 191 I/O6 (io), 192 I/O7 (io), 193 I/O8 (io), 194 I/O9 (io), 196 I/O10 (io), 197 I/O11 (io), 198 I/O12 (io), 199 I/O13 (io), 200 I/O14 (io), 202 I/O15 (io), 203 I/O16 (io), 204 I/O17 (io), 205 I/O18 (io), 206 I/O19 (io)
part B pins: 1 GND (power), 7 TCK (in), 13 GND (power), 19 NC, 25 CLK0/IN0 (in), 26 VCC0 (power), 27 GND (power), 28 NC, 29 CLK1/IN1 (in), 40 GND (power), 46 NC, 52 VCC0 (power), 53 GND (power), 59 TMS (in), 65 GND (power), 71 NC, 77 IN2 (in), 78 VCC0 (power), 79 GND (power), 80 VCC (power), 91 GND (power), 97 GND (power), 98 TDO (out), 104 VCC0 (power), 105 GND (power), 116 GND (power), 122 NC, 128 CLK2/IN3 (in), 129 GND (power), 130 VCC0 (power), 131 GND (power), 132 VCC (power), 133 CLK3/IN4 (in), 144 GND (power), 150 TDI (in), 156 VCC0 (power), 157 GND (power), 158 NC, 169 GND (power), 175 NC, 181 NC, 182 VCC (power), 183 GND (power), 184 VCC0 (power), 195 GND (power), 201 NC, 207 VCC0 (power), 208 VCC (power)

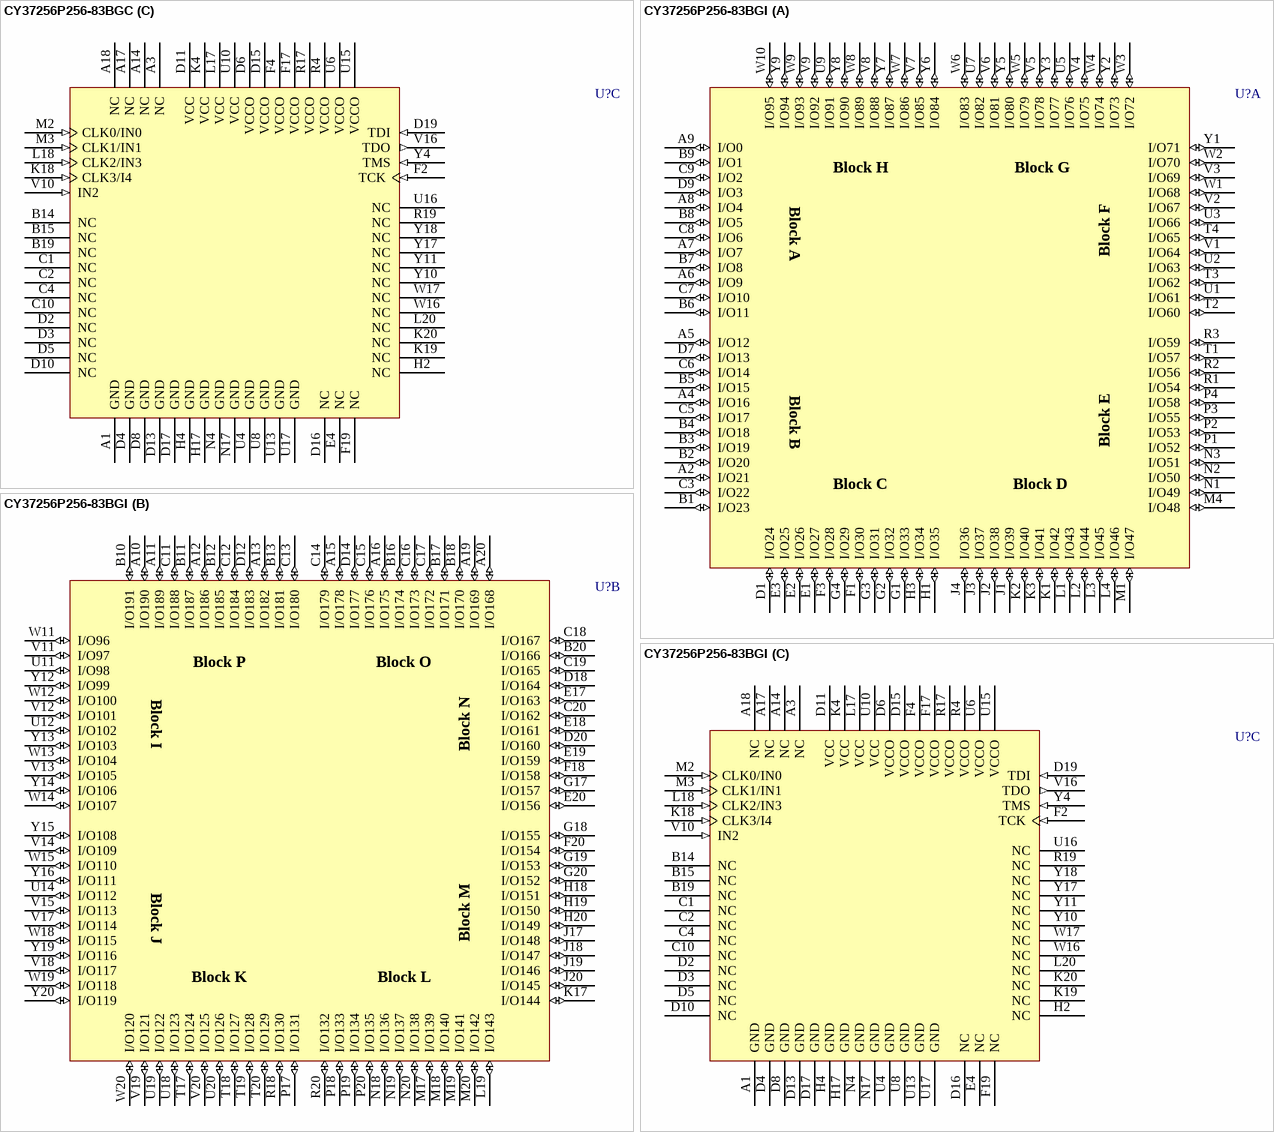
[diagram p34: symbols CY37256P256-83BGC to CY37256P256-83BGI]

## CY37256P256-83BGC
designator U?
Ultra37000 5V, ISR High-Performance CPLD
footprint BG256 (BGA, 292-Leads, Body 27x27mm, Pitch 1.27mm)
3D model CY37256P256-BG256 (292-Ball Ball Grid Array 1.27 mm Pitch)
part A pins: A2 I/O21 (io), A4 I/O16 (io), A5 I/O12 (io), A6 I/O9 (io), A7 I/O7 (io), A8 I/O4 (io), A9 I/O0 (io), B1 I/O23 (io), B2 I/O20 (io), B3 I/O19 (io), B4 I/O18 (io), B5 I/O15 (io), B6 I/O11 (io), B7 I/O8 (io), B8 I/O5 (io), B9 I/O1 (io), C3 I/O22 (io), C5 I/O17 (io), C6 I/O14 (io), C7 I/O10 (io), C8 I/O6 (io), C9 I/O2 (io), D1 I/O24 (io), D7 I/O13 (io), D9 I/O3 (io), E1 I/O27 (io), E2 I/O26 (io), E3 I/O25 (io), F1 I/O30 (io), F3 I/O28 (io), G1 I/O33 (io), G2 I/O32 (io), G3 I/O31 (io), G4 I/O29 (io), H1 I/O35 (io), H3 I/O34 (io), J1 I/O39 (io), J2 I/O38 (io), J3 I/O37 (io), J4 I/O36 (io), K1 I/O42 (io), K2 I/O40 (io), K3 I/O41 (io), L1 I/O43 (io), L2 I/O44 (io), L3 I/O45 (io), L4 I/O46 (io), M1 I/O47 (io), M4 I/O48 (io), N1 I/O49 (io), N2 I/O50 (io), N3 I/O51 (io), P1 I/O52 (io), P2 I/O53 (io), P3 I/O55 (io), P4 I/O58 (io), R1 I/O54 (io), R2 I/O56 (io), R3 I/O59 (io), T1 I/O57 (io), T2 I/O60 (io), T3 I/O62 (io), T4 I/O65 (io), U1 I/O61 (io), U2 I/O63 (io), U3 I/O66 (io), U5 I/O76 (io), U7 I/O82 (io), U9 I/O91 (io), V1 I/O64 (io), V2 I/O67 (io), V3 I/O69 (io), V4 I/O75 (io), V5 I/O78 (io), V6 I/O81 (io), V7 I/O85 (io), V8 I/O88 (io), V9 I/O92 (io), W1 I/O68 (io), W2 I/O70 (io), W3 I/O72 (io), W4 I/O74 (io), W5 I/O79 (io), W6 I/O83 (io), W7 I/O86 (io), W8 I/O89 (io), W9 I/O93 (io), W10 I/O95 (io), Y1 I/O71 (io), Y2 I/O73 (io), Y3 I/O77 (io), Y5 I/O80 (io), Y6 I/O84 (io), Y7 I/O87 (io), Y8 I/O90 (io), Y9 I/O94 (io)
part B pins: A10 I/O190 (io), A11 I/O189 (io), A12 I/O186 (io), A13 I/O182 (io), A15 I/O178 (io), A16 I/O175 (io), A19 I/O169 (io), A20 I/O168 (io), B10 I/O191 (io), B11 I/O187 (io), B12 I/O185 (io), B13 I/O181 (io), B16 I/O174 (io), B17 I/O171 (io), B18 I/O170 (io), B20 I/O166 (io), C11 I/O188 (io), C12 I/O184 (io), C13 I/O180 (io), C14 I/O179 (io), C15 I/O176 (io), C16 I/O173 (io), C17 I/O172 (io), C18 I/O167 (io), C19 I/O165 (io), C20 I/O162 (io), D12 I/O183 (io), D14 I/O177 (io), D18 I/O164 (io), D20 I/O160 (io), E17 I/O163 (io), E18 I/O161 (io), E19 I/O159 (io), E20 I/O156 (io), F18 I/O158 (io), F20 I/O154 (io), G17 I/O157 (io), G18 I/O155 (io), G19 I/O153 (io), G20 I/O152 (io), H18 I/O151 (io), H19 I/O150 (io), H20 I/O149 (io), J17 I/O148 (io), J18 I/O147 (io), J19 I/O146 (io), J20 I/O145 (io), K17 I/O144 (io), L19 I/O143 (io), M17 I/O139 (io), M18 I/O140 (io), M19 I/O141 (io), M20 I/O142 (io), N18 I/O136 (io), N19 I/O137 (io), N20 I/O138 (io), P17 I/O131 (io), P18 I/O133 (io), P19 I/O134 (io), P20 I/O135 (io), R18 I/O130 (io), R20 I/O132 (io), T17 I/O124 (io), T18 I/O127 (io), T19 I/O128 (io), T20 I/O129 (io), U11 I/O98 (io), U12 I/O102 (io), U14 I/O112 (io), U18 I/O123 (io), U19 I/O122 (io), U20 I/O126 (io), V11 I/O97 (io), V12 I/O101 (io), V13 I/O105 (io), V14 I/O109 (io), V15 I/O113 (io), V17 I/O114 (io), V18 I/O117 (io), V19 I/O121 (io), V20 I/O125 (io), W11 I/O96 (io), W12 I/O100 (io), W13 I/O104 (io), W14 I/O107 (io), W15 I/O110 (io), W18 I/O115 (io), W19 I/O118 (io), W20 I/O120 (io), Y12 I/O99 (io), Y13 I/O103 (io), Y14 I/O106 (io), Y15 I/O108 (io), Y16 I/O111 (io), Y19 I/O116 (io), Y20 I/O119 (io)
part C pins: A1 GND (power), A3 NC, A14 NC, A17 NC, A18 NC, B14 NC, B15 NC, B19 NC, C1 NC, C2 NC, C4 NC, C10 NC, D2 NC, D3 NC, D4 GND (power), D5 NC, D6 VCCO (power), D8 GND (power), D10 NC, D11 VCC (power), D13 GND (power), D15 VCCO (power), D16 NC, D17 GND (power), D19 TDI (in), E4 NC, F2 TCK (in), F4 VCCO (power), F17 VCCO (power), F19 NC, H2 NC, H4 GND (power), H17 GND (power), K4 VCC (power), K18 CLK3/I4 (in), K19 NC, K20 NC, L17 VCC (power), L18 CLK2/IN3 (in), L20 NC, M2 CLK0/IN0 (in), M3 CLK1/IN1 (in), N4 GND (power), N17 GND (power), R4 VCCO (power), R17 VCCO (power), R19 NC, U4 GND (power), U6 VCCO (power), U8 GND (power), U10 VCC (power), U13 GND (power), U15 VCCO (power), U16 NC, U17 GND (power), V10 IN2 (in), V16 TDO (out), W16 NC, W17 NC, Y4 TMS (in), Y10 NC, Y11 NC, Y17 NC, Y18 NC

## CY37256P256-83BGI
designator U?
Ultra37000 5V, ISR High-Performance CPLD
footprint BG256 (BGA, 292-Leads, Body 27x27mm, Pitch 1.27mm)
3D model CY37256P256-BG256 (292-Ball Ball Grid Array 1.27 mm Pitch)
part A pins: A2 I/O21 (io), A4 I/O16 (io), A5 I/O12 (io), A6 I/O9 (io), A7 I/O7 (io), A8 I/O4 (io), A9 I/O0 (io), B1 I/O23 (io), B2 I/O20 (io), B3 I/O19 (io), B4 I/O18 (io), B5 I/O15 (io), B6 I/O11 (io), B7 I/O8 (io), B8 I/O5 (io), B9 I/O1 (io), C3 I/O22 (io), C5 I/O17 (io), C6 I/O14 (io), C7 I/O10 (io), C8 I/O6 (io), C9 I/O2 (io), D1 I/O24 (io), D7 I/O13 (io), D9 I/O3 (io), E1 I/O27 (io), E2 I/O26 (io), E3 I/O25 (io), F1 I/O30 (io), F3 I/O28 (io), G1 I/O33 (io), G2 I/O32 (io), G3 I/O31 (io), G4 I/O29 (io), H1 I/O35 (io), H3 I/O34 (io), J1 I/O39 (io), J2 I/O38 (io), J3 I/O37 (io), J4 I/O36 (io), K1 I/O42 (io), K2 I/O40 (io), K3 I/O41 (io), L1 I/O43 (io), L2 I/O44 (io), L3 I/O45 (io), L4 I/O46 (io), M1 I/O47 (io), M4 I/O48 (io), N1 I/O49 (io), N2 I/O50 (io), N3 I/O51 (io), P1 I/O52 (io), P2 I/O53 (io), P3 I/O55 (io), P4 I/O58 (io), R1 I/O54 (io), R2 I/O56 (io), R3 I/O59 (io), T1 I/O57 (io), T2 I/O60 (io), T3 I/O62 (io), T4 I/O65 (io), U1 I/O61 (io), U2 I/O63 (io), U3 I/O66 (io), U5 I/O76 (io), U7 I/O82 (io), U9 I/O91 (io), V1 I/O64 (io), V2 I/O67 (io), V3 I/O69 (io), V4 I/O75 (io), V5 I/O78 (io), V6 I/O81 (io), V7 I/O85 (io), V8 I/O88 (io), V9 I/O92 (io), W1 I/O68 (io), W2 I/O70 (io), W3 I/O72 (io), W4 I/O74 (io), W5 I/O79 (io), W6 I/O83 (io), W7 I/O86 (io), W8 I/O89 (io), W9 I/O93 (io), W10 I/O95 (io), Y1 I/O71 (io), Y2 I/O73 (io), Y3 I/O77 (io), Y5 I/O80 (io), Y6 I/O84 (io), Y7 I/O87 (io), Y8 I/O90 (io), Y9 I/O94 (io)
part B pins: A10 I/O190 (io), A11 I/O189 (io), A12 I/O186 (io), A13 I/O182 (io), A15 I/O178 (io), A16 I/O175 (io), A19 I/O169 (io), A20 I/O168 (io), B10 I/O191 (io), B11 I/O187 (io), B12 I/O185 (io), B13 I/O181 (io), B16 I/O174 (io), B17 I/O171 (io), B18 I/O170 (io), B20 I/O166 (io), C11 I/O188 (io), C12 I/O184 (io), C13 I/O180 (io), C14 I/O179 (io), C15 I/O176 (io), C16 I/O173 (io), C17 I/O172 (io), C18 I/O167 (io), C19 I/O165 (io), C20 I/O162 (io), D12 I/O183 (io), D14 I/O177 (io), D18 I/O164 (io), D20 I/O160 (io), E17 I/O163 (io), E18 I/O161 (io), E19 I/O159 (io), E20 I/O156 (io), F18 I/O158 (io), F20 I/O154 (io), G17 I/O157 (io), G18 I/O155 (io), G19 I/O153 (io), G20 I/O152 (io), H18 I/O151 (io), H19 I/O150 (io), H20 I/O149 (io), J17 I/O148 (io), J18 I/O147 (io), J19 I/O146 (io), J20 I/O145 (io), K17 I/O144 (io), L19 I/O143 (io), M17 I/O139 (io), M18 I/O140 (io), M19 I/O141 (io), M20 I/O142 (io), N18 I/O136 (io), N19 I/O137 (io), N20 I/O138 (io), P17 I/O131 (io), P18 I/O133 (io), P19 I/O134 (io), P20 I/O135 (io), R18 I/O130 (io), R20 I/O132 (io), T17 I/O124 (io), T18 I/O127 (io), T19 I/O128 (io), T20 I/O129 (io), U11 I/O98 (io), U12 I/O102 (io), U14 I/O112 (io), U18 I/O123 (io), U19 I/O122 (io), U20 I/O126 (io), V11 I/O97 (io), V12 I/O101 (io), V13 I/O105 (io), V14 I/O109 (io), V15 I/O113 (io), V17 I/O114 (io), V18 I/O117 (io), V19 I/O121 (io), V20 I/O125 (io), W11 I/O96 (io), W12 I/O100 (io), W13 I/O104 (io), W14 I/O107 (io), W15 I/O110 (io), W18 I/O115 (io), W19 I/O118 (io), W20 I/O120 (io), Y12 I/O99 (io), Y13 I/O103 (io), Y14 I/O106 (io), Y15 I/O108 (io), Y16 I/O111 (io), Y19 I/O116 (io), Y20 I/O119 (io)
part C pins: A1 GND (power), A3 NC, A14 NC, A17 NC, A18 NC, B14 NC, B15 NC, B19 NC, C1 NC, C2 NC, C4 NC, C10 NC, D2 NC, D3 NC, D4 GND (power), D5 NC, D6 VCCO (power), D8 GND (power), D10 NC, D11 VCC (power), D13 GND (power), D15 VCCO (power), D16 NC, D17 GND (power), D19 TDI (in), E4 NC, F2 TCK (in), F4 VCCO (power), F17 VCCO (power), F19 NC, H2 NC, H4 GND (power), H17 GND (power), K4 VCC (power), K18 CLK3/I4 (in), K19 NC, K20 NC, L17 VCC (power), L18 CLK2/IN3 (in), L20 NC, M2 CLK0/IN0 (in), M3 CLK1/IN1 (in), N4 GND (power), N17 GND (power), R4 VCCO (power), R17 VCCO (power), R19 NC, U4 GND (power), U6 VCCO (power), U8 GND (power), U10 VCC (power), U13 GND (power), U15 VCCO (power), U16 NC, U17 GND (power), V10 IN2 (in), V16 TDO (out), W16 NC, W17 NC, Y4 TMS (in), Y10 NC, Y11 NC, Y17 NC, Y18 NC

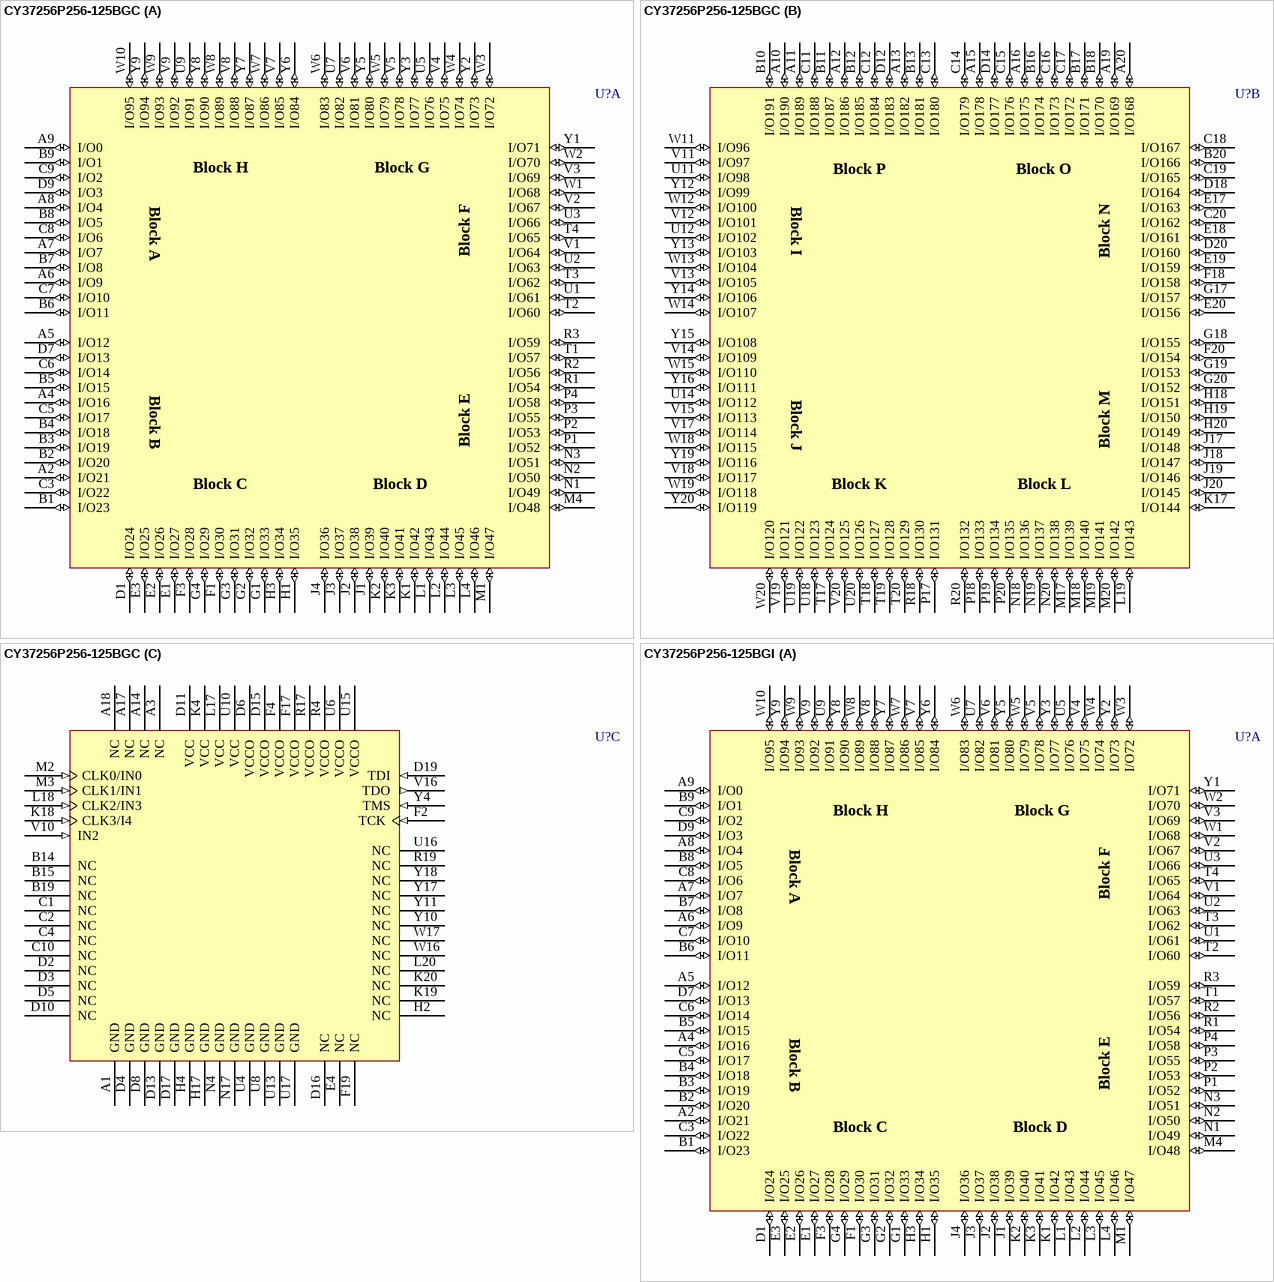
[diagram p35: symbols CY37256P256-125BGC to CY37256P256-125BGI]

## CY37256P256-125BGC
designator U?
Ultra37000 5V, ISR High-Performance CPLD
footprint BG256 (BGA, 292-Leads, Body 27x27mm, Pitch 1.27mm)
3D model CY37256P256-BG256 (292-Ball Ball Grid Array 1.27 mm Pitch)
part A pins: A2 I/O21 (io), A4 I/O16 (io), A5 I/O12 (io), A6 I/O9 (io), A7 I/O7 (io), A8 I/O4 (io), A9 I/O0 (io), B1 I/O23 (io), B2 I/O20 (io), B3 I/O19 (io), B4 I/O18 (io), B5 I/O15 (io), B6 I/O11 (io), B7 I/O8 (io), B8 I/O5 (io), B9 I/O1 (io), C3 I/O22 (io), C5 I/O17 (io), C6 I/O14 (io), C7 I/O10 (io), C8 I/O6 (io), C9 I/O2 (io), D1 I/O24 (io), D7 I/O13 (io), D9 I/O3 (io), E1 I/O27 (io), E2 I/O26 (io), E3 I/O25 (io), F1 I/O30 (io), F3 I/O28 (io), G1 I/O33 (io), G2 I/O32 (io), G3 I/O31 (io), G4 I/O29 (io), H1 I/O35 (io), H3 I/O34 (io), J1 I/O39 (io), J2 I/O38 (io), J3 I/O37 (io), J4 I/O36 (io), K1 I/O42 (io), K2 I/O40 (io), K3 I/O41 (io), L1 I/O43 (io), L2 I/O44 (io), L3 I/O45 (io), L4 I/O46 (io), M1 I/O47 (io), M4 I/O48 (io), N1 I/O49 (io), N2 I/O50 (io), N3 I/O51 (io), P1 I/O52 (io), P2 I/O53 (io), P3 I/O55 (io), P4 I/O58 (io), R1 I/O54 (io), R2 I/O56 (io), R3 I/O59 (io), T1 I/O57 (io), T2 I/O60 (io), T3 I/O62 (io), T4 I/O65 (io), U1 I/O61 (io), U2 I/O63 (io), U3 I/O66 (io), U5 I/O76 (io), U7 I/O82 (io), U9 I/O91 (io), V1 I/O64 (io), V2 I/O67 (io), V3 I/O69 (io), V4 I/O75 (io), V5 I/O78 (io), V6 I/O81 (io), V7 I/O85 (io), V8 I/O88 (io), V9 I/O92 (io), W1 I/O68 (io), W2 I/O70 (io), W3 I/O72 (io), W4 I/O74 (io), W5 I/O79 (io), W6 I/O83 (io), W7 I/O86 (io), W8 I/O89 (io), W9 I/O93 (io), W10 I/O95 (io), Y1 I/O71 (io), Y2 I/O73 (io), Y3 I/O77 (io), Y5 I/O80 (io), Y6 I/O84 (io), Y7 I/O87 (io), Y8 I/O90 (io), Y9 I/O94 (io)
part B pins: A10 I/O190 (io), A11 I/O189 (io), A12 I/O186 (io), A13 I/O182 (io), A15 I/O178 (io), A16 I/O175 (io), A19 I/O169 (io), A20 I/O168 (io), B10 I/O191 (io), B11 I/O187 (io), B12 I/O185 (io), B13 I/O181 (io), B16 I/O174 (io), B17 I/O171 (io), B18 I/O170 (io), B20 I/O166 (io), C11 I/O188 (io), C12 I/O184 (io), C13 I/O180 (io), C14 I/O179 (io), C15 I/O176 (io), C16 I/O173 (io), C17 I/O172 (io), C18 I/O167 (io), C19 I/O165 (io), C20 I/O162 (io), D12 I/O183 (io), D14 I/O177 (io), D18 I/O164 (io), D20 I/O160 (io), E17 I/O163 (io), E18 I/O161 (io), E19 I/O159 (io), E20 I/O156 (io), F18 I/O158 (io), F20 I/O154 (io), G17 I/O157 (io), G18 I/O155 (io), G19 I/O153 (io), G20 I/O152 (io), H18 I/O151 (io), H19 I/O150 (io), H20 I/O149 (io), J17 I/O148 (io), J18 I/O147 (io), J19 I/O146 (io), J20 I/O145 (io), K17 I/O144 (io), L19 I/O143 (io), M17 I/O139 (io), M18 I/O140 (io), M19 I/O141 (io), M20 I/O142 (io), N18 I/O136 (io), N19 I/O137 (io), N20 I/O138 (io), P17 I/O131 (io), P18 I/O133 (io), P19 I/O134 (io), P20 I/O135 (io), R18 I/O130 (io), R20 I/O132 (io), T17 I/O124 (io), T18 I/O127 (io), T19 I/O128 (io), T20 I/O129 (io), U11 I/O98 (io), U12 I/O102 (io), U14 I/O112 (io), U18 I/O123 (io), U19 I/O122 (io), U20 I/O126 (io), V11 I/O97 (io), V12 I/O101 (io), V13 I/O105 (io), V14 I/O109 (io), V15 I/O113 (io), V17 I/O114 (io), V18 I/O117 (io), V19 I/O121 (io), V20 I/O125 (io), W11 I/O96 (io), W12 I/O100 (io), W13 I/O104 (io), W14 I/O107 (io), W15 I/O110 (io), W18 I/O115 (io), W19 I/O118 (io), W20 I/O120 (io), Y12 I/O99 (io), Y13 I/O103 (io), Y14 I/O106 (io), Y15 I/O108 (io), Y16 I/O111 (io), Y19 I/O116 (io), Y20 I/O119 (io)
part C pins: A1 GND (power), A3 NC, A14 NC, A17 NC, A18 NC, B14 NC, B15 NC, B19 NC, C1 NC, C2 NC, C4 NC, C10 NC, D2 NC, D3 NC, D4 GND (power), D5 NC, D6 VCCO (power), D8 GND (power), D10 NC, D11 VCC (power), D13 GND (power), D15 VCCO (power), D16 NC, D17 GND (power), D19 TDI (in), E4 NC, F2 TCK (in), F4 VCCO (power), F17 VCCO (power), F19 NC, H2 NC, H4 GND (power), H17 GND (power), K4 VCC (power), K18 CLK3/I4 (in), K19 NC, K20 NC, L17 VCC (power), L18 CLK2/IN3 (in), L20 NC, M2 CLK0/IN0 (in), M3 CLK1/IN1 (in), N4 GND (power), N17 GND (power), R4 VCCO (power), R17 VCCO (power), R19 NC, U4 GND (power), U6 VCCO (power), U8 GND (power), U10 VCC (power), U13 GND (power), U15 VCCO (power), U16 NC, U17 GND (power), V10 IN2 (in), V16 TDO (out), W16 NC, W17 NC, Y4 TMS (in), Y10 NC, Y11 NC, Y17 NC, Y18 NC

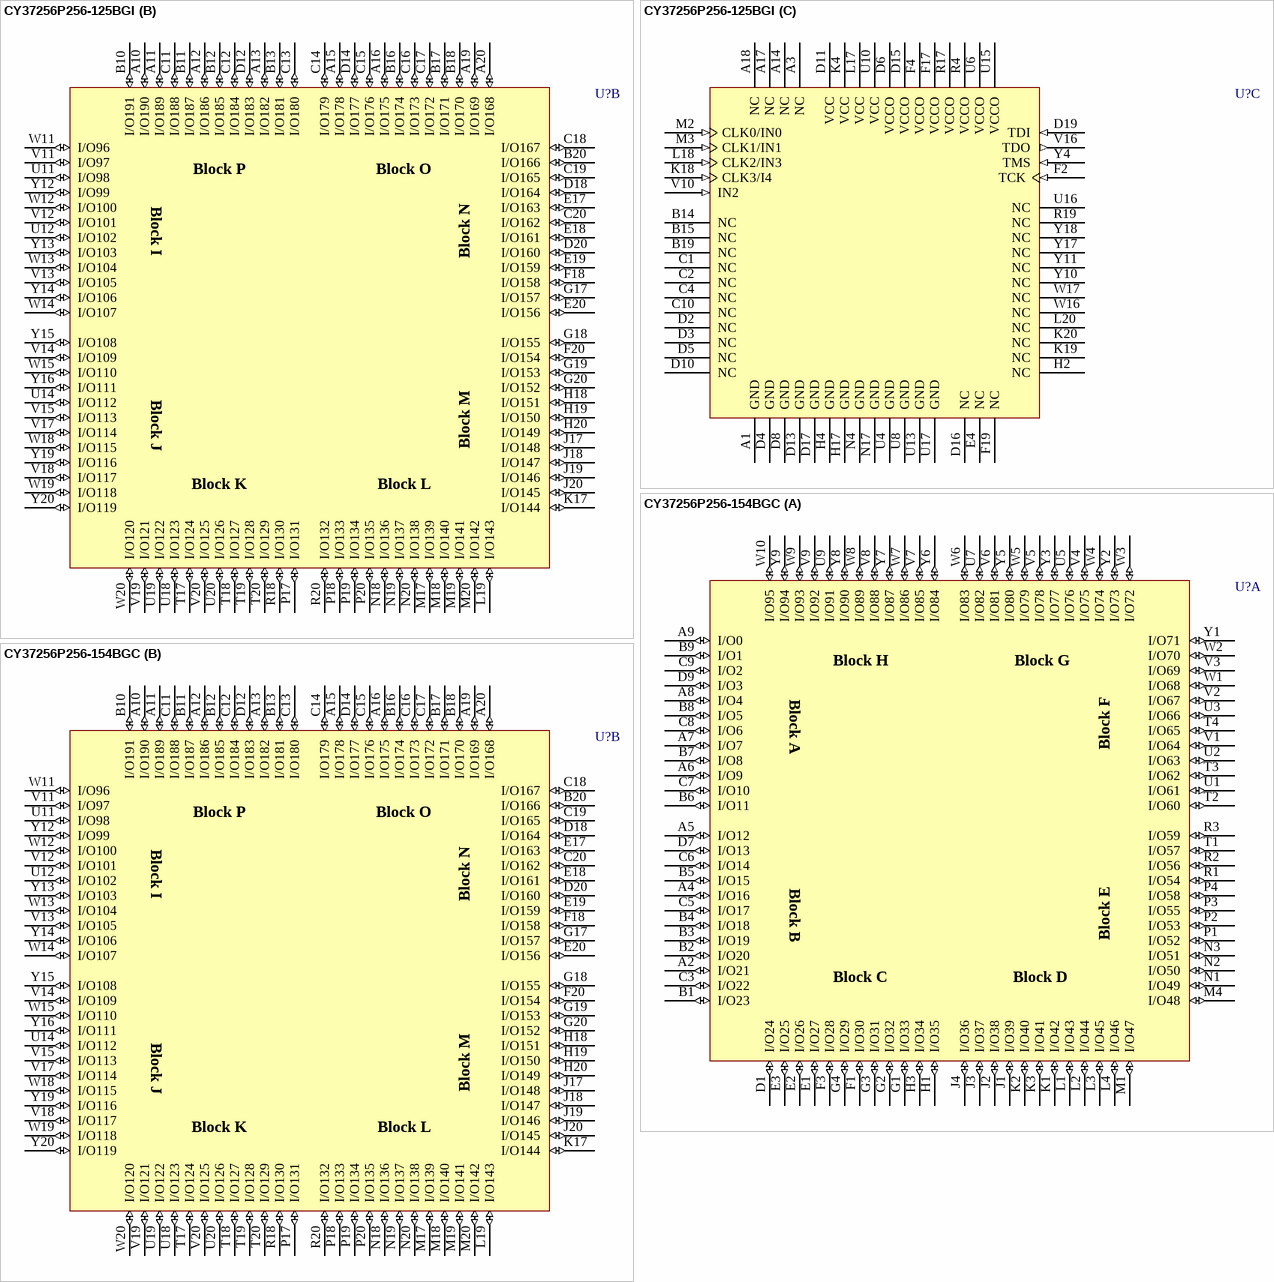
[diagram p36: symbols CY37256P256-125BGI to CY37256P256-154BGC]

## CY37256P256-125BGI
designator U?
Ultra37000 5V, ISR High-Performance CPLD
footprint BG256 (BGA, 292-Leads, Body 27x27mm, Pitch 1.27mm)
3D model CY37256P256-BG256 (292-Ball Ball Grid Array 1.27 mm Pitch)
part A pins: A2 I/O21 (io), A4 I/O16 (io), A5 I/O12 (io), A6 I/O9 (io), A7 I/O7 (io), A8 I/O4 (io), A9 I/O0 (io), B1 I/O23 (io), B2 I/O20 (io), B3 I/O19 (io), B4 I/O18 (io), B5 I/O15 (io), B6 I/O11 (io), B7 I/O8 (io), B8 I/O5 (io), B9 I/O1 (io), C3 I/O22 (io), C5 I/O17 (io), C6 I/O14 (io), C7 I/O10 (io), C8 I/O6 (io), C9 I/O2 (io), D1 I/O24 (io), D7 I/O13 (io), D9 I/O3 (io), E1 I/O27 (io), E2 I/O26 (io), E3 I/O25 (io), F1 I/O30 (io), F3 I/O28 (io), G1 I/O33 (io), G2 I/O32 (io), G3 I/O31 (io), G4 I/O29 (io), H1 I/O35 (io), H3 I/O34 (io), J1 I/O39 (io), J2 I/O38 (io), J3 I/O37 (io), J4 I/O36 (io), K1 I/O42 (io), K2 I/O40 (io), K3 I/O41 (io), L1 I/O43 (io), L2 I/O44 (io), L3 I/O45 (io), L4 I/O46 (io), M1 I/O47 (io), M4 I/O48 (io), N1 I/O49 (io), N2 I/O50 (io), N3 I/O51 (io), P1 I/O52 (io), P2 I/O53 (io), P3 I/O55 (io), P4 I/O58 (io), R1 I/O54 (io), R2 I/O56 (io), R3 I/O59 (io), T1 I/O57 (io), T2 I/O60 (io), T3 I/O62 (io), T4 I/O65 (io), U1 I/O61 (io), U2 I/O63 (io), U3 I/O66 (io), U5 I/O76 (io), U7 I/O82 (io), U9 I/O91 (io), V1 I/O64 (io), V2 I/O67 (io), V3 I/O69 (io), V4 I/O75 (io), V5 I/O78 (io), V6 I/O81 (io), V7 I/O85 (io), V8 I/O88 (io), V9 I/O92 (io), W1 I/O68 (io), W2 I/O70 (io), W3 I/O72 (io), W4 I/O74 (io), W5 I/O79 (io), W6 I/O83 (io), W7 I/O86 (io), W8 I/O89 (io), W9 I/O93 (io), W10 I/O95 (io), Y1 I/O71 (io), Y2 I/O73 (io), Y3 I/O77 (io), Y5 I/O80 (io), Y6 I/O84 (io), Y7 I/O87 (io), Y8 I/O90 (io), Y9 I/O94 (io)
part B pins: A10 I/O190 (io), A11 I/O189 (io), A12 I/O186 (io), A13 I/O182 (io), A15 I/O178 (io), A16 I/O175 (io), A19 I/O169 (io), A20 I/O168 (io), B10 I/O191 (io), B11 I/O187 (io), B12 I/O185 (io), B13 I/O181 (io), B16 I/O174 (io), B17 I/O171 (io), B18 I/O170 (io), B20 I/O166 (io), C11 I/O188 (io), C12 I/O184 (io), C13 I/O180 (io), C14 I/O179 (io), C15 I/O176 (io), C16 I/O173 (io), C17 I/O172 (io), C18 I/O167 (io), C19 I/O165 (io), C20 I/O162 (io), D12 I/O183 (io), D14 I/O177 (io), D18 I/O164 (io), D20 I/O160 (io), E17 I/O163 (io), E18 I/O161 (io), E19 I/O159 (io), E20 I/O156 (io), F18 I/O158 (io), F20 I/O154 (io), G17 I/O157 (io), G18 I/O155 (io), G19 I/O153 (io), G20 I/O152 (io), H18 I/O151 (io), H19 I/O150 (io), H20 I/O149 (io), J17 I/O148 (io), J18 I/O147 (io), J19 I/O146 (io), J20 I/O145 (io), K17 I/O144 (io), L19 I/O143 (io), M17 I/O139 (io), M18 I/O140 (io), M19 I/O141 (io), M20 I/O142 (io), N18 I/O136 (io), N19 I/O137 (io), N20 I/O138 (io), P17 I/O131 (io), P18 I/O133 (io), P19 I/O134 (io), P20 I/O135 (io), R18 I/O130 (io), R20 I/O132 (io), T17 I/O124 (io), T18 I/O127 (io), T19 I/O128 (io), T20 I/O129 (io), U11 I/O98 (io), U12 I/O102 (io), U14 I/O112 (io), U18 I/O123 (io), U19 I/O122 (io), U20 I/O126 (io), V11 I/O97 (io), V12 I/O101 (io), V13 I/O105 (io), V14 I/O109 (io), V15 I/O113 (io), V17 I/O114 (io), V18 I/O117 (io), V19 I/O121 (io), V20 I/O125 (io), W11 I/O96 (io), W12 I/O100 (io), W13 I/O104 (io), W14 I/O107 (io), W15 I/O110 (io), W18 I/O115 (io), W19 I/O118 (io), W20 I/O120 (io), Y12 I/O99 (io), Y13 I/O103 (io), Y14 I/O106 (io), Y15 I/O108 (io), Y16 I/O111 (io), Y19 I/O116 (io), Y20 I/O119 (io)
part C pins: A1 GND (power), A3 NC, A14 NC, A17 NC, A18 NC, B14 NC, B15 NC, B19 NC, C1 NC, C2 NC, C4 NC, C10 NC, D2 NC, D3 NC, D4 GND (power), D5 NC, D6 VCCO (power), D8 GND (power), D10 NC, D11 VCC (power), D13 GND (power), D15 VCCO (power), D16 NC, D17 GND (power), D19 TDI (in), E4 NC, F2 TCK (in), F4 VCCO (power), F17 VCCO (power), F19 NC, H2 NC, H4 GND (power), H17 GND (power), K4 VCC (power), K18 CLK3/I4 (in), K19 NC, K20 NC, L17 VCC (power), L18 CLK2/IN3 (in), L20 NC, M2 CLK0/IN0 (in), M3 CLK1/IN1 (in), N4 GND (power), N17 GND (power), R4 VCCO (power), R17 VCCO (power), R19 NC, U4 GND (power), U6 VCCO (power), U8 GND (power), U10 VCC (power), U13 GND (power), U15 VCCO (power), U16 NC, U17 GND (power), V10 IN2 (in), V16 TDO (out), W16 NC, W17 NC, Y4 TMS (in), Y10 NC, Y11 NC, Y17 NC, Y18 NC

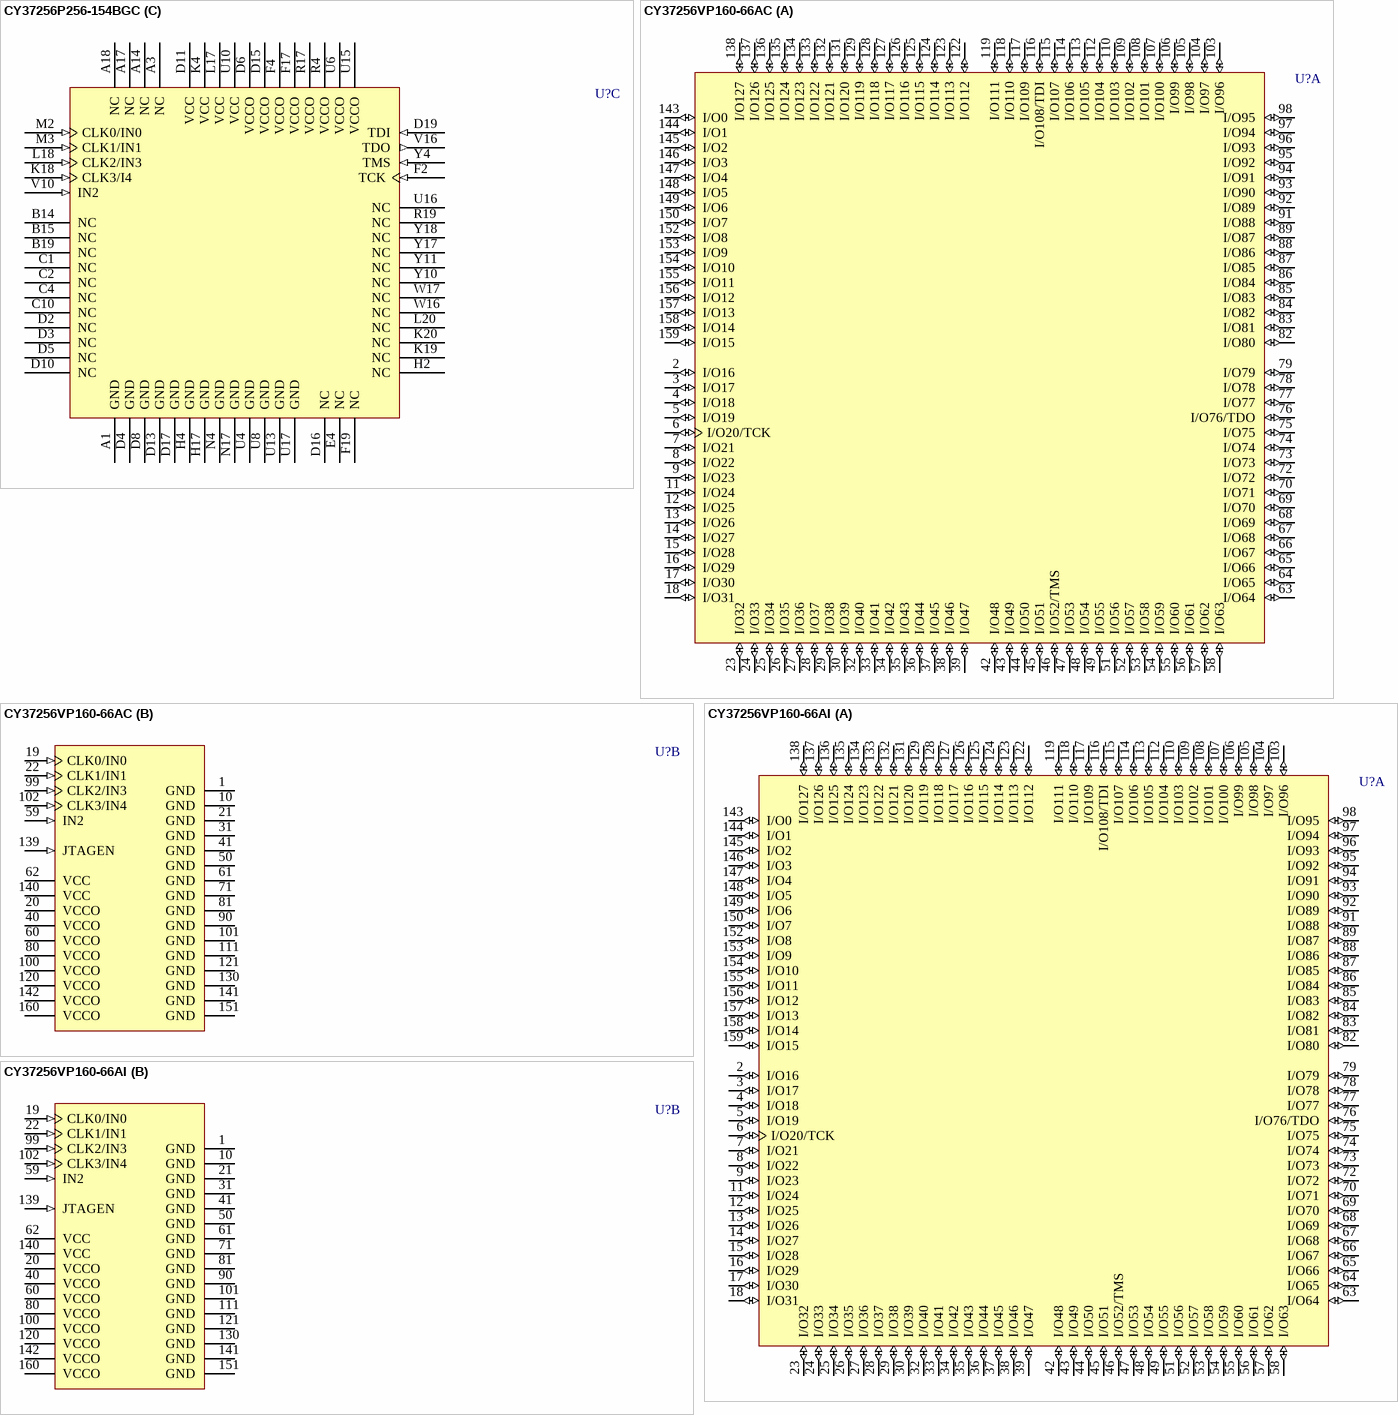
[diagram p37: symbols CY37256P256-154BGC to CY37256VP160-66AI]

## CY37256P256-154BGC
designator U?
Ultra37000 5V, ISR High-Performance CPLD
footprint BG256 (BGA, 292-Leads, Body 27x27mm, Pitch 1.27mm)
3D model CY37256P256-BG256 (292-Ball Ball Grid Array 1.27 mm Pitch)
part A pins: A2 I/O21 (io), A4 I/O16 (io), A5 I/O12 (io), A6 I/O9 (io), A7 I/O7 (io), A8 I/O4 (io), A9 I/O0 (io), B1 I/O23 (io), B2 I/O20 (io), B3 I/O19 (io), B4 I/O18 (io), B5 I/O15 (io), B6 I/O11 (io), B7 I/O8 (io), B8 I/O5 (io), B9 I/O1 (io), C3 I/O22 (io), C5 I/O17 (io), C6 I/O14 (io), C7 I/O10 (io), C8 I/O6 (io), C9 I/O2 (io), D1 I/O24 (io), D7 I/O13 (io), D9 I/O3 (io), E1 I/O27 (io), E2 I/O26 (io), E3 I/O25 (io), F1 I/O30 (io), F3 I/O28 (io), G1 I/O33 (io), G2 I/O32 (io), G3 I/O31 (io), G4 I/O29 (io), H1 I/O35 (io), H3 I/O34 (io), J1 I/O39 (io), J2 I/O38 (io), J3 I/O37 (io), J4 I/O36 (io), K1 I/O42 (io), K2 I/O40 (io), K3 I/O41 (io), L1 I/O43 (io), L2 I/O44 (io), L3 I/O45 (io), L4 I/O46 (io), M1 I/O47 (io), M4 I/O48 (io), N1 I/O49 (io), N2 I/O50 (io), N3 I/O51 (io), P1 I/O52 (io), P2 I/O53 (io), P3 I/O55 (io), P4 I/O58 (io), R1 I/O54 (io), R2 I/O56 (io), R3 I/O59 (io), T1 I/O57 (io), T2 I/O60 (io), T3 I/O62 (io), T4 I/O65 (io), U1 I/O61 (io), U2 I/O63 (io), U3 I/O66 (io), U5 I/O76 (io), U7 I/O82 (io), U9 I/O91 (io), V1 I/O64 (io), V2 I/O67 (io), V3 I/O69 (io), V4 I/O75 (io), V5 I/O78 (io), V6 I/O81 (io), V7 I/O85 (io), V8 I/O88 (io), V9 I/O92 (io), W1 I/O68 (io), W2 I/O70 (io), W3 I/O72 (io), W4 I/O74 (io), W5 I/O79 (io), W6 I/O83 (io), W7 I/O86 (io), W8 I/O89 (io), W9 I/O93 (io), W10 I/O95 (io), Y1 I/O71 (io), Y2 I/O73 (io), Y3 I/O77 (io), Y5 I/O80 (io), Y6 I/O84 (io), Y7 I/O87 (io), Y8 I/O90 (io), Y9 I/O94 (io)
part B pins: A10 I/O190 (io), A11 I/O189 (io), A12 I/O186 (io), A13 I/O182 (io), A15 I/O178 (io), A16 I/O175 (io), A19 I/O169 (io), A20 I/O168 (io), B10 I/O191 (io), B11 I/O187 (io), B12 I/O185 (io), B13 I/O181 (io), B16 I/O174 (io), B17 I/O171 (io), B18 I/O170 (io), B20 I/O166 (io), C11 I/O188 (io), C12 I/O184 (io), C13 I/O180 (io), C14 I/O179 (io), C15 I/O176 (io), C16 I/O173 (io), C17 I/O172 (io), C18 I/O167 (io), C19 I/O165 (io), C20 I/O162 (io), D12 I/O183 (io), D14 I/O177 (io), D18 I/O164 (io), D20 I/O160 (io), E17 I/O163 (io), E18 I/O161 (io), E19 I/O159 (io), E20 I/O156 (io), F18 I/O158 (io), F20 I/O154 (io), G17 I/O157 (io), G18 I/O155 (io), G19 I/O153 (io), G20 I/O152 (io), H18 I/O151 (io), H19 I/O150 (io), H20 I/O149 (io), J17 I/O148 (io), J18 I/O147 (io), J19 I/O146 (io), J20 I/O145 (io), K17 I/O144 (io), L19 I/O143 (io), M17 I/O139 (io), M18 I/O140 (io), M19 I/O141 (io), M20 I/O142 (io), N18 I/O136 (io), N19 I/O137 (io), N20 I/O138 (io), P17 I/O131 (io), P18 I/O133 (io), P19 I/O134 (io), P20 I/O135 (io), R18 I/O130 (io), R20 I/O132 (io), T17 I/O124 (io), T18 I/O127 (io), T19 I/O128 (io), T20 I/O129 (io), U11 I/O98 (io), U12 I/O102 (io), U14 I/O112 (io), U18 I/O123 (io), U19 I/O122 (io), U20 I/O126 (io), V11 I/O97 (io), V12 I/O101 (io), V13 I/O105 (io), V14 I/O109 (io), V15 I/O113 (io), V17 I/O114 (io), V18 I/O117 (io), V19 I/O121 (io), V20 I/O125 (io), W11 I/O96 (io), W12 I/O100 (io), W13 I/O104 (io), W14 I/O107 (io), W15 I/O110 (io), W18 I/O115 (io), W19 I/O118 (io), W20 I/O120 (io), Y12 I/O99 (io), Y13 I/O103 (io), Y14 I/O106 (io), Y15 I/O108 (io), Y16 I/O111 (io), Y19 I/O116 (io), Y20 I/O119 (io)
part C pins: A1 GND (power), A3 NC, A14 NC, A17 NC, A18 NC, B14 NC, B15 NC, B19 NC, C1 NC, C2 NC, C4 NC, C10 NC, D2 NC, D3 NC, D4 GND (power), D5 NC, D6 VCCO (power), D8 GND (power), D10 NC, D11 VCC (power), D13 GND (power), D15 VCCO (power), D16 NC, D17 GND (power), D19 TDI (in), E4 NC, F2 TCK (in), F4 VCCO (power), F17 VCCO (power), F19 NC, H2 NC, H4 GND (power), H17 GND (power), K4 VCC (power), K18 CLK3/I4 (in), K19 NC, K20 NC, L17 VCC (power), L18 CLK2/IN3 (in), L20 NC, M2 CLK0/IN0 (in), M3 CLK1/IN1 (in), N4 GND (power), N17 GND (power), R4 VCCO (power), R17 VCCO (power), R19 NC, U4 GND (power), U6 VCCO (power), U8 GND (power), U10 VCC (power), U13 GND (power), U15 VCCO (power), U16 NC, U17 GND (power), V10 IN2 (in), V16 TDO (out), W16 NC, W17 NC, Y4 TMS (in), Y10 NC, Y11 NC, Y17 NC, Y18 NC

## CY37256VP160-66AC
designator U?
Ultra37000 3.3V, ISR High-Performance CPLD
footprint A160_N (Thin QFP, 160-Leads, Body 24x24mm, Pitch 0.5mm, IPC Medium Density)
footprint A160_L (Thin QFP, 160-Leads, Body 24x24mm, Pitch 0.5mm, IPC High Density)
footprint A160_M (Thin QFP, 160-Leads, Body 24x24mm, Pitch 0.5mm, IPC Low Density)
3D model CY37256VP160-A160 (160-Pin Thin Quad Flat Pack 0.5 mm Pitch)
part A pins: 2 I/O16 (io), 3 I/O17 (io), 4 I/O18 (io), 5 I/O19 (io), 6 I/O20/TCK (io), 7 I/O21 (io), 8 I/O22 (io), 9 I/O23 (io), 11 I/O24 (io), 12 I/O25 (io), 13 I/O26 (io), 14 I/O27 (io), 15 I/O28 (io), 16 I/O29 (io), 17 I/O30 (io), 18 I/O31 (io), 23 I/O32 (io), 24 I/O33 (io), 25 I/O34 (io), 26 I/O35 (io), 27 I/O36 (io), 28 I/O37 (io), 29 I/O38 (io), 30 I/O39 (io), 32 I/O40 (io), 33 I/O41 (io), 34 I/O42 (io), 35 I/O43 (io), 36 I/O44 (io), 37 I/O45 (io), 38 I/O46 (io), 39 I/O47 (io), 42 I/O48 (io), 43 I/O49 (io), 44 I/O50 (io), 45 I/O51 (io), 46 I/O52/TMS (io), 47 I/O53 (io), 48 I/O54 (io), 49 I/O55 (io), 51 I/O56 (io), 52 I/O57 (io), 53 I/O58 (io), 54 I/O59 (io), 55 I/O60 (io), 56 I/O61 (io), 57 I/O62 (io), 58 I/O63 (io), 63 I/O64 (io), 64 I/O65 (io), 65 I/O66 (io), 66 I/O67 (io), 67 I/O68 (io), 68 I/O69 (io), 69 I/O70 (io), 70 I/O71 (io), 72 I/O72 (io), 73 I/O73 (io), 74 I/O74 (io), 75 I/O75 (io), 76 I/O76/TDO (io), 77 I/O77 (io), 78 I/O78 (io), 79 I/O79 (io), 82 I/O80 (io), 83 I/O81 (io), 84 I/O82 (io), 85 I/O83 (io), 86 I/O84 (io), 87 I/O85 (io), 88 I/O86 (io), 89 I/O87 (io), 91 I/O88 (io), 92 I/O89 (io), 93 I/O90 (io), 94 I/O91 (io), 95 I/O92 (io), 96 I/O93 (io), 97 I/O94 (io), 98 I/O95 (io), 103 I/O96 (io), 104 I/O97 (io), 105 I/O98 (io), 106 I/O99 (io), 107 I/O100 (io), 108 I/O101 (io), 109 I/O102 (io), 110 I/O103 (io), 112 I/O104 (io), 113 I/O105 (io), 114 I/O106 (io), 115 I/O107 (io), 116 I/O108/TDI (io), 117 I/O109 (io), 118 I/O110 (io), 119 I/O111 (io), 122 I/O112 (io), 123 I/O113 (io), 124 I/O114 (io), 125 I/O115 (io), 126 I/O116 (io), 127 I/O117 (io), 128 I/O118 (io), 129 I/O119 (io), 131 I/O120 (io), 132 I/O121 (io), 133 I/O122 (io), 134 I/O123 (io), 135 I/O124 (io), 136 I/O125 (io), 137 I/O126 (io), 138 I/O127 (io), 143 I/O0 (io), 144 I/O1 (io), 145 I/O2 (io), 146 I/O3 (io), 147 I/O4 (io), 148 I/O5 (io), 149 I/O6 (io), 150 I/O7 (io), 152 I/O8 (io), 153 I/O9 (io), 154 I/O10 (io), 155 I/O11 (io), 156 I/O12 (io), 157 I/O13 (io), 158 I/O14 (io), 159 I/O15 (io)
part B pins: 1 GND (power), 10 GND (power), 19 CLK0/IN0 (in), 20 VCCO (power), 21 GND (power), 22 CLK1/IN1 (in), 31 GND (power), 40 VCCO (power), 41 GND (power), 50 GND (power), 59 IN2 (in), 60 VCCO (power), 61 GND (power), 62 VCC (power), 71 GND (power), 80 VCCO (power), 81 GND (power), 90 GND (power), 99 CLK2/IN3 (in), 100 VCCO (power), 101 GND (power), 102 CLK3/IN4 (in), 111 GND (power), 120 VCCO (power), 121 GND (power), 130 GND (power), 139 JTAGEN (in), 140 VCC (power), 141 GND (power), 142 VCCO (power), 151 GND (power), 160 VCCO (power)

## CY37256VP160-66AI
designator U?
Ultra37000 3.3V, ISR High-Performance CPLD
footprint A160_N (Thin QFP, 160-Leads, Body 24x24mm, Pitch 0.5mm, IPC Medium Density)
footprint A160_L (Thin QFP, 160-Leads, Body 24x24mm, Pitch 0.5mm, IPC High Density)
footprint A160_M (Thin QFP, 160-Leads, Body 24x24mm, Pitch 0.5mm, IPC Low Density)
3D model CY37256VP160-A160 (160-Pin Thin Quad Flat Pack 0.5 mm Pitch)
part A pins: 2 I/O16 (io), 3 I/O17 (io), 4 I/O18 (io), 5 I/O19 (io), 6 I/O20/TCK (io), 7 I/O21 (io), 8 I/O22 (io), 9 I/O23 (io), 11 I/O24 (io), 12 I/O25 (io), 13 I/O26 (io), 14 I/O27 (io), 15 I/O28 (io), 16 I/O29 (io), 17 I/O30 (io), 18 I/O31 (io), 23 I/O32 (io), 24 I/O33 (io), 25 I/O34 (io), 26 I/O35 (io), 27 I/O36 (io), 28 I/O37 (io), 29 I/O38 (io), 30 I/O39 (io), 32 I/O40 (io), 33 I/O41 (io), 34 I/O42 (io), 35 I/O43 (io), 36 I/O44 (io), 37 I/O45 (io), 38 I/O46 (io), 39 I/O47 (io), 42 I/O48 (io), 43 I/O49 (io), 44 I/O50 (io), 45 I/O51 (io), 46 I/O52/TMS (io), 47 I/O53 (io), 48 I/O54 (io), 49 I/O55 (io), 51 I/O56 (io), 52 I/O57 (io), 53 I/O58 (io), 54 I/O59 (io), 55 I/O60 (io), 56 I/O61 (io), 57 I/O62 (io), 58 I/O63 (io), 63 I/O64 (io), 64 I/O65 (io), 65 I/O66 (io), 66 I/O67 (io), 67 I/O68 (io), 68 I/O69 (io), 69 I/O70 (io), 70 I/O71 (io), 72 I/O72 (io), 73 I/O73 (io), 74 I/O74 (io), 75 I/O75 (io), 76 I/O76/TDO (io), 77 I/O77 (io), 78 I/O78 (io), 79 I/O79 (io), 82 I/O80 (io), 83 I/O81 (io), 84 I/O82 (io), 85 I/O83 (io), 86 I/O84 (io), 87 I/O85 (io), 88 I/O86 (io), 89 I/O87 (io), 91 I/O88 (io), 92 I/O89 (io), 93 I/O90 (io), 94 I/O91 (io), 95 I/O92 (io), 96 I/O93 (io), 97 I/O94 (io), 98 I/O95 (io), 103 I/O96 (io), 104 I/O97 (io), 105 I/O98 (io), 106 I/O99 (io), 107 I/O100 (io), 108 I/O101 (io), 109 I/O102 (io), 110 I/O103 (io), 112 I/O104 (io), 113 I/O105 (io), 114 I/O106 (io), 115 I/O107 (io), 116 I/O108/TDI (io), 117 I/O109 (io), 118 I/O110 (io), 119 I/O111 (io), 122 I/O112 (io), 123 I/O113 (io), 124 I/O114 (io), 125 I/O115 (io), 126 I/O116 (io), 127 I/O117 (io), 128 I/O118 (io), 129 I/O119 (io), 131 I/O120 (io), 132 I/O121 (io), 133 I/O122 (io), 134 I/O123 (io), 135 I/O124 (io), 136 I/O125 (io), 137 I/O126 (io), 138 I/O127 (io), 143 I/O0 (io), 144 I/O1 (io), 145 I/O2 (io), 146 I/O3 (io), 147 I/O4 (io), 148 I/O5 (io), 149 I/O6 (io), 150 I/O7 (io), 152 I/O8 (io), 153 I/O9 (io), 154 I/O10 (io), 155 I/O11 (io), 156 I/O12 (io), 157 I/O13 (io), 158 I/O14 (io), 159 I/O15 (io)
part B pins: 1 GND (power), 10 GND (power), 19 CLK0/IN0 (in), 20 VCCO (power), 21 GND (power), 22 CLK1/IN1 (in), 31 GND (power), 40 VCCO (power), 41 GND (power), 50 GND (power), 59 IN2 (in), 60 VCCO (power), 61 GND (power), 62 VCC (power), 71 GND (power), 80 VCCO (power), 81 GND (power), 90 GND (power), 99 CLK2/IN3 (in), 100 VCCO (power), 101 GND (power), 102 CLK3/IN4 (in), 111 GND (power), 120 VCCO (power), 121 GND (power), 130 GND (power), 139 JTAGEN (in), 140 VCC (power), 141 GND (power), 142 VCCO (power), 151 GND (power), 160 VCCO (power)

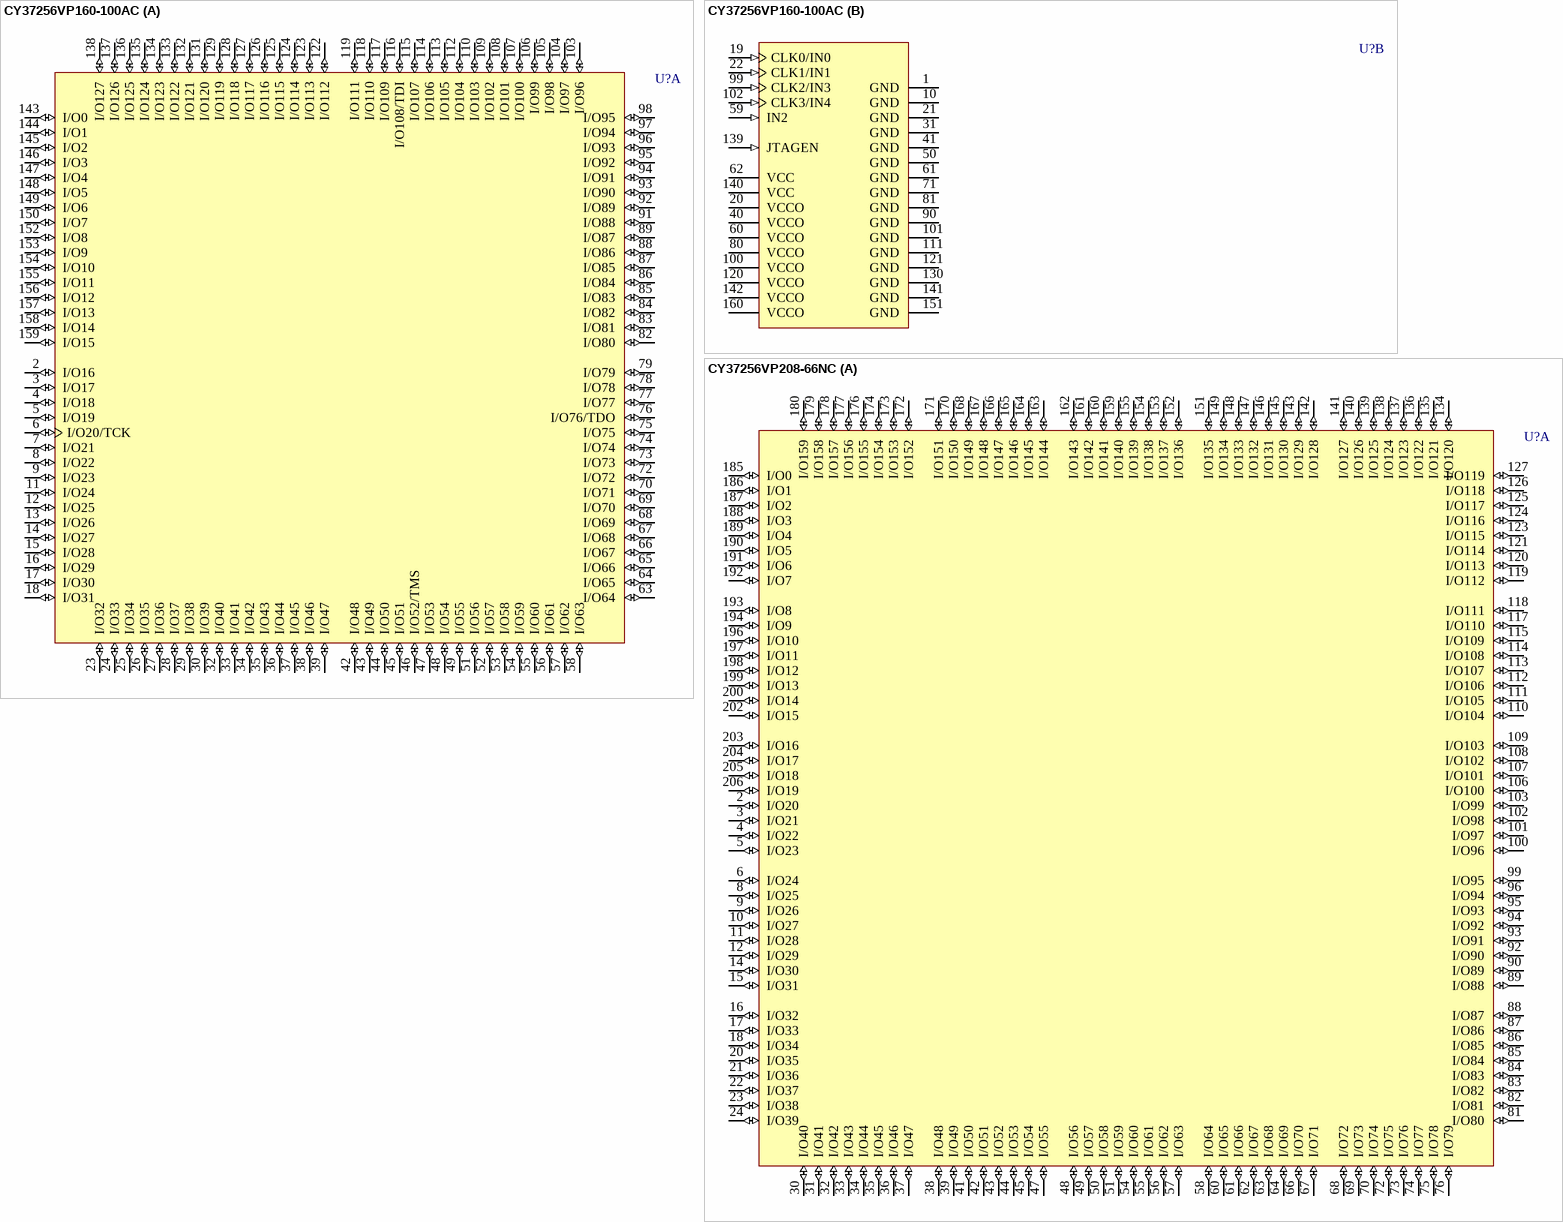
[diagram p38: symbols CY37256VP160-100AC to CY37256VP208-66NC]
